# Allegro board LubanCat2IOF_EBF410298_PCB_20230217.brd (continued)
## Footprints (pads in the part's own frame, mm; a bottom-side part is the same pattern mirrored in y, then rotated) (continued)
USB-A-D
  round 1.651 hole 1: 1(3.5,-6.5) 2(1,-6.5) 3(-1,-6.5) 4(-3.5,-6.5) 7(3.5,-3.5) 8(1,-3.5) 9(-1,-3.5) 10(-3.5,-3.5)
  round 3.3 hole 2: 5(-6.55,-6.5) 6(6.55,-6.5) 11(-6.55,-0.7) 12(6.55,-0.7)
USON_10
  rect 0.3x0.55 smd: 1(-1,-0.4) 2(-0.5,-0.4) 4(0.5,-0.4) 5(1,-0.4) 6(1,0.4) 7(0.5,0.4) 9(-0.5,0.4) 10(-1,0.4)
  rect 0.4x0.55 smd: 3(0,-0.4) 8(0,0.4)
XH2P54-4P
  rect 1.45x1.45 hole 0.85: 1(-3.81,0)
  round 1.45 hole 0.85: 2(-1.27,0) 3(1.27,0) 4(3.81,0)
ZH1P5MM_TH_2P
  round 1.05 hole 0.65: 1(-0.75,0) 2(0.75,0)

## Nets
1V05_AVDD_PHY0: C84.1 C85.1 C86.1 C87.1 R114.2 U18.3(AVDD10_2) U18.8(AVDD10_1) U18.38(AVDD10)
1V05_AVDD_PHY1: C105.1 C106.1 C107.1 C108.1 R141.2 U19.3(AVDD10_2) U19.8(AVDD10_1) U19.38(AVDD10)
1V05_DVDD_PHY0: C82.1 C83.1 R113.1 U18.21(DVDD10)
1V05_DVDD_PHY1: C103.1 C104.1 R140.1 U19.21(DVDD10)
1V05_PHY0: C74.1 C75.1 L9.2 R113.2 R114.1
1V05_PHY1: C96.1 C97.1 L13.2 R140.2 R141.1
1V8_DVDD_PHY0: C72.1 C73.1 C81.1 L10.1 R88.1 R89.1 R90.1 R101.1 R102.1 R107.1 U18.28(DVDD_RG)
1V8_DVDD_PHY1: C94.1 C95.1 C102.1 L14.1 R115.1 R116.1 R117.1 R128.1 R129.1 R136.1 U19.28(DVDD_RG)
3V3_AVDD_PHY0: C91.1 C92.1 C93.1 L12.1 U18.11(AVDD33_1) U18.40(AVDD33)
3V3_AVDD_PHY1: C112.1 C113.1 C114.1 L16.1 U19.11(AVDD33_1) U19.40(AVDD33)
3V3_DVDD_PHY0: C88.1 C89.1 C90.1 L11.1 R28.2 R103.1 R109.2 R110.2 R184.1 U18.29(DVDD33)
3V3_DVDD_PHY1: C109.1 C110.1 C111.1 L15.1 R130.1 R133.2 R138.2 R139.2 R238.1 U19.29(DVDD33)
12V: C5.1 C6.1 C7.1 C8.1 C9.1 C10.1 C18.1 C19.1 C27.1 C160.1 C179.1 C180.1 C181.1 C182.1 C209.1 C210.1 C218.1 F1.2 J3.1 J29.26 J29.27 J29.28 J29.29 Q10.2(SOURCE) R205.1 R225.2 U1.3(VIN) U2.3(VIN) U5.3(VIN) U16.3(VIN) U41.3(VIN)
12V_IN: F1.1 J39.4
GND: C3.2 C4.2 C5.2 C6.2 C7.2 C8.2 C9.2 C10.2 C12.2 C13.2 C15.2 C16.2 C17.2 C18.2 C19.2 C21.2 C22.2 C23.2 C25.2 C26.2 C27.2 C28.2 C30.2 C31.2 C33.2 C34.2 C35.2 C36.2 C37.2 C38.2 C39.2 C40.2 C41.2 C42.2 C43.2 C44.2 C45.2 C46.2 C47.2 C48.2 C51.2 C52.2 C55.2 C56.2 C57.2 C58.2 C59.2 C63.2 C64.2 C65.2 C66.2 C67.2 C70.2 C71.2 C72.2 C73.2 C74.2 C75.2 C76.2 C77.2 C78.2 C79.2 C80.2 C81.2 C82.2 C83.2 C84.2 C85.2 C86.2 C87.2 C88.2 C89.2 C90.2 C91.2 C92.2 C93.2 C94.2 C95.2 C96.2 C97.2 C98.2 C99.2 C100.2 C101.2 C102.2 C103.2 C104.2 C105.2 C106.2 C107.2 C108.2 C109.2 C110.2 C111.2 C112.2 C113.2 C114.2 C115.2 C116.2 C117.2 C118.2 C119.2 C120.2 C121.2 C122.2 C129.2 C130.2 C131.2 C132.2 C133.2 C134.2 C135.2 C136.2 C137.2 C138.2 C141.2 C144.2 C145.2 C146.2 C147.2 C148.2 C149.2 C150.2 C151.2 C152.2 C153.2 C154.2 C155.2 C156.2 C157.2 C158.2 C159.2 C160.2 C161.2 C162.2 C163.2 C164.2 C165.2 C166.2 C167.2 C168.2 C169.2 C170.2 C171.2 C172.2 C173.2 C174.2 C175.2 C176.2 C179.2 C180.2 C181.2 C182.2 C183.2 C184.2 C185.2 C186.2 C187.2 C188.2 C189.2 C190.2 C191.2 C192.2 C193.2 C194.2 C195.2 C196.2 C197.2 C198.2 C199.2 C200.2 C201.2 C202.2 C203.2 C204.2 C207.2 C208.2 C209.2 C210.2 C212.2 C213.2 C216.2 C218.2 D1.1 D2.1 D3.1 D6.2 D7.2 D8.2 D9.2 D10.2 D11.2 D12.2 D13.2 D15.1 D16.1 D17.1 D18.1 D19.2 D20.1(A) D23.2 D24.1 D25.2 D26.2 D28.1 D29.2 D30.2 D31.2 D32.2 D33.2 D34.2 J1.2 J1.3 J2.3 J3.2 J3.4 J3.6 J4.6(VSS) J4.10(GND10) J4.11(GND11) J4.12(GND12) J4.13(GND13) J6.2 J8.2 J8.5 J9.4 J11.10(CHS) J12.4 J15.6 J16.2 J17.1(CONFIG_3) J17.3(GND1) J17.9(GND2) J17.15(GND3) J17.21(CONFIG_0) J17.27(GND4) J17.33(GND5) J17.39(GND_6) J17.45(GND_7) J17.51(GND_8) J17.57(GND_9) J17.71(GND_10) J17.73(GND_11) J17.75(CONFIG_2) J17.76(G1) J17.77(G2) J18.10(CHS) J19.4(GND1) J19.7(GND2) J19.13(GND1) J19.16(NC3) J20.4(GND) J20.10(GND) J21.2 J21.5 J21.8 J21.11 J21.17 J22.4 J22.18 J22.21 J22.23 J22.24 J22.25 J22.26 J23.6 J23.7 J23.8 J23.16 J23.19 J23.22 J23.25 J23.28 J23.31 J23.32 J24.4 J24.23 J24.24 J24.25 J24.26 J26.6 J26.7 J26.8 J26.16 J26.19 J26.22 J26.25 J26.28 J26.31 J26.32 J28.6 J29.2 J29.5 J29.8 J29.11 J29.15 J29.16 J29.18 J29.19 J29.20 J29.21 J29.31 J29.32 J33.1 J34.1(GND1) J34.4(GND2) J34.7(GND3) J34.S1(SH1) J34.S2(SH2) J35.4(GND9) J35.9(GND1) J35.15(GND2) J35.18(GND10) J35.21(GND3) J35.26(GND11) J35.27(GND4) J35.29(GND5) J35.34(GND12) J35.35(GND6) J35.37(GND7) J35.40(GND13) J35.43(GND8) J35.50(GND14) J35.53 J35.54 J36.A1(GND1) J36.A12(GND2) J36.B1(GND4) J36.B12(GND3) J38.7 J38.8 J38.9 J38.10 J38.11 J38.12 J38.18 J38.22 J38.24 J38.25 J38.26 J38.27 J38.32 J38.38 J38.39 J38.46 J38.53 J38.62 J38.67 J38.72 J38.81 J38.87 J38.90 J38.91 J38.96 J38.100 J38.106 J38.107 J38.116 J38.117 J38.122 J38.128 J38.135 J38.138 J38.141 J38.144 J38.154 J38.159 J38.164 J38.166 J38.167 J38.176 J38.194 J38.195 J38.204 J38.205 J38.211 J38.214 J38.221 J38.228 J38.229 J38.238 J38.239 J38.248 J38.249 J38.258 J38.263 J38.272 J38.285 J38.288 J38.294 J38.299 J38.300 J38.306 J38.311 J38.312 J38.315 J38.316 J39.2 J39.3 L2.2 L19.2 L20.2 L21.2 LED1.2(CATHODE) Q4.2(EMITTER) Q14.2(SOURCE) R3.2 R7.2 R8.2 R12.2 R13.2 R15.2 R17.2 R27.2 R40.2 R41.2 R69.2 R70.2 R74.2 R75.2 R79.2 R82.2 R97.2 R98.2 R99.2 R100.2 R106.2 R108.2 R112.2 R121.2 R125.2 R126.2 R127.2 R131.2 R135.2 R137.2 R142.2 R143.2 R144.2 R155.2 R157.2 R159.2 R162.2 R163.2 R171.2 R173.2 R175.2 R176.2 R177.2 R183.2 R186.2 R188.1 R190.2 R192.2 R196.2 R197.2 R198.2 R199.2 R202.2 R203.2 R207.2 R212.2 R215.2 R216.2 R220.2 R234.2 R237.2 SS5.1(NC_1) SS6.1(NC_1) SS7.1(NC_1) SS8.1(NC_1) SS9.1(NC_1) SS10.1(NC_1) SS11.1(NC_1) SW1.1(A1) SW1.3(GND1) SW2.1(A1) SW2.3(GND1) SW3.1(A1) SW3.3(GND1) U1.1(GND) U2.1(GND) U3.1(GND1) U3.4(GND2) U4.1(\\O\E) U4.3(GND) U5.1(GND) U6.4(GND) U7.1(GND) U8.5(GND) U9.2(GND) U9.8(S) U10.2(GND) U10.8(S) U11.15(GND) U12.1(\\O\E) U12.3(GND) U13.5(GND) U14.5(GND) U14.8(SH1) U14.9(SH2) U14.10(SH3) U14.11(SH4) U15.2 U16.1(GND) U17.4(GND) U18.41(GND) U19.41(GND) U20.1(GND) U21.9(GNDXD) U21.16(GNDODA) U22.3(GND1) U22.8(GND2) U23.3(GND1) U23.8(GND2) U24.2(GND) U25.2(GND) U26.2(GND) U28.25(VSS) U29.2(GND) U30.3(GND1) U30.8(GND2) U31.3(GND1) U31.8(GND2) U32.3(GND1) U32.8(GND2) U33.2(GND) U34.2(GND) U35.2(GND) U36.2(GND) U37.2(GND) U38.2(GND) U39.2(GND) U40.2(GND) U41.1(GND) Y1.2(GND1) Y1.4(GND2) Y2.2(GND1) Y2.4(GND2) Y3.2(GND1) Y3.4(GND2) Y4.2(GND1) Y4.4(GND2) Z1.2 Z2.2
VCC3V3_SD: C28.1 C30.1 J4.4(VDD) J38.17 J38.19
VCC5V0_SYS: C24.2 C25.1 C26.1 J38.1 J38.2 J38.3 J38.4 J38.5 J38.6 L3.2 R4.1 R11.2
VCC5V0_USB: C140.2 C141.1 C159.1 L17.2 R235.2 U24.5(IN) U25.5(IN) U26.5(IN) U29.5(IN)
VCC5V0_USB20_HOST2: C144.1 C145.1 J19.10(VBUS) U24.1(OUT)
VCC5V0_USB20_HUB: C154.1 C155.1 C161.1 C162.1 C164.1 C165.1 J20.1(VBUS) J20.7(VBUS) U28.19(VDD5) U29.1(OUT)
VCC5V0_USB30_HOST: C148.1 C149.1 J19.1(VBUS) U26.1(OUT)
VCC_1V8: C22.1 C23.1 J38.13 J38.15 L10.2 L14.2 Q1.1(GATE) Q2.1(GATE) R24.1 R25.1 R45.1 R46.1 U6.8(VCC)
VCCA_1V8: J38.14 J38.16 R219.1
VCCIO_ACODEC: J38.21 J38.23 R210.1 R213.1
VDD_3V3: C12.1 C13.1 C14.2 C17.1 C21.1 C37.1 C40.1 D21.2 J3.5 L5.1 L6.1 L7.2 L11.2 L12.2 L15.2 L16.2 L35.2 Q6.1(GATE) Q8.1(GATE) R2.2 R6.2 R31.1 R32.1 R33.1 R35.1 R47.1 R48.1 R66.2 R72.1 R146.1 R147.1 R178.1 R180.1 R181.1 R236.2 U4.5(VCC) U9.5(VIO) U10.5(VIO) U12.5(VCC) U35.5(IN) U37.5(IN) U38.5(IN) U40.5(IN)
VDD_3V3_EDP_LCD: C183.1 C184.1 J29.12 J29.13 R187.1 U37.1(OUT)
VDD_3V3_EDP_TP: C202.1 C203.1 J28.1 R193.1 R194.1 U38.1(OUT)
VDD_5V: C2.2 C3.1 C4.1 C36.1 C38.1 C41.1 C43.1 C46.1 C79.1 C80.1 D14.1 J3.3 L1.2 Q3.2(SOURCE) Q7.1(GATE) R1.2 R9.1 U7.3(VIN) U9.3(VCC) U10.3(VCC) U20.3(VIN) U33.5(IN) U34.5(IN) U36.5(IN) U39.5(IN)
VDD_CAM0_5V: C169.1 C170.1 C171.1 J22.1 J22.2 J22.3 U33.1(OUT)
VDD_CAM1_5V: C173.1 C174.1 C175.1 J24.1 J24.2 J24.3 U36.1(OUT)
VDD_LCD0_3V3: C185.1 C190.1 C191.1 J23.4 J23.5 R167.1 R222.1 U35.1(OUT)
VDD_LCD0_5V: C186.1 C187.1 C188.1 J23.1 J23.2 J23.3 U34.1(OUT)
VDD_LCD1_3V3: C196.1 C198.1 C199.1 J26.4 J26.5 R223.1 R224.1 U40.1(OUT)
VDD_LCD1_5V: C194.1 C195.1 C197.1 J26.1 J26.2 J26.3 U39.1(OUT)
BAT_RTC: C67.1 D21.1 D24.2 J16.1
CAM0_NRST: J22.22 J38.158
CAM0_PWDN: J22.15 J38.156
CAM0_PWR_EN: J38.309 R174.1
CAM1_NRST: J24.22 J38.162
CAM1_PWDN: J24.15 J38.160
CAM1_PWR_EN: J38.307 R185.1
CAN1_H: J5.1 R39.1 U9.7(CANH)
CAN1_L: J5.2 R39.2 U9.6(CANL)
CAN1_RX_M1: J38.275 U9.4(RXD)
CAN1_TX_M1: J38.273 U9.1(TXD)
CAN2_H: J5.3 R42.1 U10.7(CANH)
CAN2_L: J5.4 R42.2 U10.6(CANL)
CAN2_RX: Q2.3(DRAIN) R48.2 U10.4(RXD)
CAN2_RX_M0: J38.172 Q2.2(SOURCE) R46.2
CAN2_TX: Q1.3(DRAIN) R47.2 U10.1(TXD)
CAN2_TX_M0: J38.174 Q1.2(SOURCE) R45.2
CC1: D27.2 J36.A5(CC1)
CC2: D27.1 J36.B5(CC2)
CTP0_INT: J23.11 J38.173 R167.2
CTP0_RST: J23.12 J38.171 R222.2
CTP1_INT: J26.11 J38.255 R223.2
CTP1_RST: J26.12 J38.257 R224.2
DGB_RX: J2.2 R36.1 Z1.1
DGB_TX: J2.1 R23.1 Z2.1
DSI0_RST: J23.15 J38.175
DSI0_TE: J38.169 R204.1
DSI1_RST: J26.15 J38.259
DSI1_TE: J38.261 R208.1
EDP_AUXN: C178.2 J29.10 R188.2
EDP_AUXP: C177.2 J29.9 R187.2
EDP_BL_EN: J29.22 J38.233
EDP_BL_PWM: J29.23 J38.177
EDP_HPDIN_M0: J29.17 J38.98
EDP_LCD_PWR_EN: J38.305 R189.2
EDP_TP_INT: J28.2 J38.253 R193.2
EDP_TP_PWR_EN: J38.303 R191.1
EDP_TP_RESET: J28.3 J38.251 R194.2
EDP_TX_AUXN: C178.1 J38.94
EDP_TX_AUXP: C177.1 J38.92
EDP_TX_D0N: J29.6 J38.76
EDP_TX_D0P: J29.7 J38.74
EDP_TX_D1N: J29.3 J38.80
EDP_TX_D1P: J29.4 J38.78
EXT_PWR_EN: J38.31 R8.1 U2.5(EN)
FAN_CTRL: J38.183 R10.1
FSPI_CLK: J38.41 U6.6(CLK)
FSPI_CS0N: J38.49 U6.1(C\S\)
FSPI_D0: J32.1 J38.51 U6.5(DI/IO0)
FSPI_D1: J38.47 U6.2(DO/IO1)
FSPI_D2: J38.43 R24.2 U6.3(W\P\/IO2)
FSPI_D3: J38.45 R25.2 U6.7(HOLD/IO3)
GMAC0_INT: J38.35 R104.1
GMAC0_MCLKINOUT: J38.89 R105.1 R106.1
GMAC0_MDC: J38.83 R101.2 U18.13(MDC)
GMAC0_MDIO: J38.85 R102.2 U18.14(MDIO)
GMAC0_RSTN: D22.2 J38.37
GMAC0_RXCLK: J38.69 R95.1 R98.1
GMAC0_RXD0: J38.75 R88.2 R91.1
GMAC0_RXD1: J38.79 R89.2 R92.1
GMAC0_RXD2: J38.71 R93.1 R97.1
GMAC0_RXD3: J38.73 R90.2 R94.1
GMAC0_RXDV_CRS: J38.77 R96.1 R99.1
GMAC0_TXCLK: J38.65 U18.20(TXC)
GMAC0_TXD0: J38.59 U18.18(TXD0)
GMAC0_TXD1: J38.57 U18.17(TXD1)
GMAC0_TXD2: J38.61 U18.16(TXD2)
GMAC0_TXD3: J38.63 U18.15(TXD3)
GMAC0_TXEN: J38.55 U18.19(TXCTL)
GMAC1_INT: J38.179 R132.1
GMAC1_MCLKINOUT_M1: J38.286 R134.1 R135.1
GMAC1_MDC_M1: J38.292 R128.2 U19.13(MDC)
GMAC1_MDIO_M1: J38.290 R129.2 U19.14(MDIO)
GMAC1_RSTN: D35.2 J38.181
GMAC1_RXCLK_M1: J38.289 R117.2 R123.1
GMAC1_RXD0_M1: J38.293 R115.2 R118.1
GMAC1_RXD1_M1: J38.297 R116.2 R119.1
GMAC1_RXD2_M1: J38.287 R120.1 R125.1
GMAC1_RXD3_M1: J38.291 R122.1 R126.1
GMAC1_RXDV_CRS_M1: J38.295 R124.1 R127.1
GMAC1_TXCLK_M1: J38.274 U19.20(TXC)
GMAC1_TXD0_M1: J38.276 U19.18(TXD0)
GMAC1_TXD1_M1: J38.278 U19.17(TXD1)
GMAC1_TXD2_M1: J38.284 U19.16(TXD2)
GMAC1_TXD3_M1: J38.282 U19.15(TXD3)
GMAC1_TXEN_M1: J38.280 U19.19(TXCTL)
HDMI_5V: C168.1 D14.2 D28.2 J21.18 R179.1 R182.1
HDMI_GND_CHASSIS: J21.G1(20) J21.G2(21) J21.G3(22) J21.G4(23) R177.1
HDMI_TX0N_PORT: J21.9 J38.198 U32.2(D1-) U32.9(NC2)
HDMI_TX0P_PORT: J21.7 J38.196 U32.1(D1+) U32.10(NC1)
HDMI_TX1N_PORT: J21.6 J38.192 U31.5(D2-) U31.6(NC4)
HDMI_TX1P_PORT: J21.4 J38.190 U31.4(D2+) U31.7(NC3)
HDMI_TX2N_PORT: J21.3 J38.188 U31.2(D1-) U31.9(NC2)
HDMI_TX2P_PORT: J21.1 J38.186 U31.1(D1+) U31.10(NC1)
HDMI_TX_CEC_PORT: D18.2 J21.13 Q7.3(DRAIN)
HDMI_TX_HPD_PORT: D15.2 J21.19 R172.2 R176.1
HDMI_TX_HPDIN: J38.184 R172.1
HDMI_TXCLKN_PORT: J21.12 J38.202 U32.5(D2-) U32.6(NC4)
HDMI_TXCLKP_PORT: J21.10 J38.200 U32.4(D2+) U32.7(NC3)
HDMI_TXDDC_SCL_PORT: D17.2 J21.15 Q6.3(DRAIN) R179.2
HDMI_TXDDC_SDA_PORT: D16.2 J21.16 Q8.3(DRAIN) R182.2
HDMITX_CEC_M0: J38.182 Q7.2(SOURCE) R180.2
HDMITX_SCL: J38.178 Q6.2(SOURCE) R178.2
HDMITX_SDA: J38.180 Q8.2(SOURCE) R181.2
HP_DET: C213.1 J38.121 R211.1
HP_SNS: J25.5 J27.5 J38.42 R212.1 R216.1
HPL_OUT: C214.1 J38.40
HPR_OUT: C215.1 J38.44
HUB_3V3: C156.1 C157.1 R164.2 R165.2 R166.2 R168.2 R169.1 U28.20(VDD33F)
I2C0_SCL: J38.111 U17.6(SCL)
I2C0_SDA: J38.109 U17.5(SDA)
I2C1_SCL: J22.6 J23.9 J38.115 R35.2
I2C1_SDA: J22.5 J23.10 J38.113 R33.2
I2C5_SCL_M0: J24.6 J26.9 J28.4 J38.313 R147.2
I2C5_SDA_M0: J24.5 J26.10 J28.5 J38.314 R146.2
LCD0_BL_PWM: J23.13 J38.187
LCD0_PWR_EN: J38.235 R195.1
LCD1_BL_PWM: J26.13 J38.185
LCD1_PWR_EN: J38.237 R200.2
LED_USR: J38.168 LED2.2(CATHODE)
M2PCIE_3V3: C69.2 C70.1 C71.1 C115.1 C116.1 C117.1 C118.1 C119.1 C120.1 C121.1 C122.1 C129.1 C130.1 C131.1 C136.1 J17.2(3.3V_1) J17.4(3.3V_2) J17.12(3.3V_3) J17.14(3.3V_4) J17.16(3.3V_5) J17.18(3.3V_6) J17.70(3.3V_7) J17.72(3.3V_8) J17.74(3.3V_9) L8.2 R73.2 R80.2 R81.2 R83.1 R84.1 R85.1 R86.1 R145.2 U21.1(VDDXD)
M2PCIE_PWR_EN: J38.133 R76.2
MDIN0_PHY0: J11.3(TD1-) U18.2(MDIN0)
MDIN0_PHY1: J18.3(TD1-) U19.2(MDIN0)
MDIN1_PHY0: J11.7(RD1-) U18.5(MDIN1)
MDIN1_PHY1: J18.7(RD1-) U19.5(MDIN1)
MDIN2_PHY0: J11.6(TD2-) U18.7(MDIN2)
MDIN2_PHY1: J18.6(TD2-) U19.7(MDIN2)
MDIN3_PHY0: J11.9(RD2-) U18.10(MDIN3)
MDIN3_PHY1: J18.9(RD2-) U19.10(MDIN3)
MDIP0_PHY0: J11.2(TD1+) U18.1(MDIP0)
MDIP0_PHY1: J18.2(TD1+) U19.1(MDIP0)
MDIP1_PHY0: J11.4(RD1+) U18.4(MDIP1)
MDIP1_PHY1: J18.4(RD1+) U19.4(MDIP1)
MDIP2_PHY0: J11.5(TD2+) U18.6(MDIP2)
MDIP2_PHY1: J18.5(TD2+) U19.6(MDIP2)
MDIP3_PHY0: J11.8(RD2+) U18.9(MDIP3)
MDIP3_PHY1: J18.8(RD2+) U19.9(MDIP3)
MIC1_INN: C217.2 D30.1 J27.3 J27.4 J30.1 J38.34 R215.1
MIC1_INP: C217.1 D29.1 J27.1 J27.2 J30.2 J38.36 R214.2
MINIPCIE_3V3: C32.1 C33.1 C34.1 C35.1 C55.1 C56.1 C57.1 C58.1 J35.2(VBAT1) J35.24(VBAT5) J35.39(VBAT2) J35.41(VBAT3) J35.52(VBAT4) L4.2 R14.1 R22.1
MINIPCIE_NWDISABLE: J38.243 R62.2
MINIPCIE_PWR_EN: J38.245 R16.1
MIPI_CSI_RX_CLK0N: J22.10 J38.240
MIPI_CSI_RX_CLK0P: J22.9 J38.242
MIPI_CSI_RX_CLK1N: J24.10 J38.244
MIPI_CSI_RX_CLK1P: J24.9 J38.246
MIPI_CSI_RX_D0N: J22.12 J38.230
MIPI_CSI_RX_D0P: J22.11 J38.232
MIPI_CSI_RX_D1N: J22.8 J38.234
MIPI_CSI_RX_D1P: J22.7 J38.236
MIPI_CSI_RX_D2N: J38.250 R227.1 R233.1
MIPI_CSI_RX_D2P: J38.252 R226.1 R232.1
MIPI_CSI_RX_D3N: J38.254 R229.1 R231.1
MIPI_CSI_RX_D3P: J38.256 R228.1 R230.1
MIPI_DSI_TX0_CLKN: J23.24 J38.216
MIPI_DSI_TX0_CLKP: J23.23 J38.218
MIPI_DSI_TX0_D0N: J23.27 J38.206
MIPI_DSI_TX0_D0P: J23.26 J38.208
MIPI_DSI_TX0_D1N: J23.21 J38.210
MIPI_DSI_TX0_D1P: J23.20 J38.212
MIPI_DSI_TX0_D2N: J23.18 J38.220
MIPI_DSI_TX0_D2P: J23.17 J38.222
MIPI_DSI_TX0_D3N: J23.30 J38.224
MIPI_DSI_TX0_D3P: J23.29 J38.226
MIPI_DSI_TX1_CLKN: J26.24 J38.207
MIPI_DSI_TX1_CLKP: J26.23 J38.209
MIPI_DSI_TX1_D0N: J26.27 J38.197
MIPI_DSI_TX1_D0P: J26.26 J38.199
MIPI_DSI_TX1_D1N: J26.21 J38.201
MIPI_DSI_TX1_D1P: J26.20 J38.203
MIPI_DSI_TX1_D2N: J26.18 J38.213
MIPI_DSI_TX1_D2P: J26.17 J38.215
MIPI_DSI_TX1_D3N: J26.30 J38.217
MIPI_DSI_TX1_D3P: J26.29 J38.219
OE: R83.2 U21.8(OE)
ON/OFF_KEY: C64.1 D2.2 J38.33 SW2.2(B1)
PCIE20_CLKREQN_M1: J38.231 R30.1
PCIE20_PERSTN_M1: J38.247 R63.2
PCIE20_REFCLKN: J35.11(VDD-EXT) J38.140
PCIE20_REFCLKP: J35.13(RESERVED) J38.142
PCIE20_RXN: J35.23(UART-RXD) J38.150
PCIE20_RXP: J35.25(UART-RTS) J38.152
PCIE20_TXN: C53.1 J38.146
PCIE20_TXP: C54.1 J38.148
PCIE20_WAKEN_M1: J38.227 R29.1
PCIE30_REFCLKN_IN: J38.139 R78.2 R79.1
PCIE30_REFCLKP_IN: J38.137 R77.2 R82.1
PCIE30_RX0N: J17.41(SATA-/B+/PERN0) J38.153
PCIE30_RX0P: J17.43(SATA-/B-/PERP0) J38.151
PCIE30_RX1N: J17.29(PERN1) J38.157
PCIE30_RX1P: J17.31(PERP1) J38.155
PCIE30_TX0N: C125.1 J38.145
PCIE30_TX0P: C126.1 J38.143
PCIE30_TX1N: C123.1 J38.149
PCIE30_TX1P: C124.1 J38.147
PCIE30X2_CLKREQN_M1: J17.52(CLKREQ#) J38.161
PCIE30X2_PERSTN_M1: J17.50(PERST#) J38.165
PCIE30X2_WAKEN_M1: J17.54(PEWAKE#) J38.163
PDN: R84.2 U21.7(PDN)
PE_TXN: C53.2 J35.31(UART-TXD)
PE_TXP: C54.2 J35.33(PERST2)
PETN0: C125.2 J17.47(SATA-/A-/PETN0)
PETN1: C123.2 J17.35(PETN1)
PETP0: C126.2 J17.49(SATA-/A+/PETP0)
PETP1: C124.2 J17.37(PETP1)
PHY0_CLKOUT125: R105.2 U18.35(CLKOUT)
PHY0_LED1: J11.14(YELA) R108.1 U18.33(LED1)
PHY0_LED2: J11.12(GRLC) R109.1 U18.34(LED2)
PHY1_CLKOUT125: R134.2 U19.35(CLKOUT)
PHY1_LED1: J18.14(YELA) R137.1 U19.33(LED1)
PHY1_LED2: J18.12(GRLC) R138.1 U19.34(LED2)
PWM3_IR: J38.189 R34.1
RECOVERY_KEY: J38.60 R26.2
REF_CLKN: C127.1 R111.2 R112.1
REF_CLKP: C128.1 R87.2 R142.1
REFCLKN: C127.2 J17.53(REFCLKN)
REFCLKP: C128.2 J17.55(REFCLKP)
RESET_KEY: C63.1 D1.2 J38.29 SW1.2(B1)
RS232_3V3: C42.1 L7.1 U11.16(VCC)
RS232_R1IN: J8.4 U11.13(R1IN)
RS232_R1OUT: J13.1 U11.12(R1OUT)
RS232_R2IN: J8.1 U11.8(R2IN)
RS232_R2OUT: J14.1 U11.9(R2OUT)
RS232_T1IN: J13.2 U11.11(T1IN)
RS232_T1OUT: J8.6 U11.14(T1OUT)
RS232_T2IN: J14.2 U11.10(T2IN)
RS232_T2OUT: J8.3 U11.7(T2OUT)
RS485_1_3V3: C39.1 D4.1 L5.2 U8.8(VCC)
RS485_1_A: J10.2 R37.1 R38.2 U8.6(A)
RS485_1_B: J10.1 R38.1 R41.1 U8.7(B)
RS485_1_DIR: J38.223 R40.1 U8.2(R\E\) U8.3(DE)
RS485_2_3V3: C44.1 D5.1 L6.2 U13.8(VCC)
RS485_2_A: J10.4 R67.1 R68.2 U13.6(A)
RS485_2_B: J10.3 R68.1 R70.1 U13.7(B)
RS485_2_DIR: J38.225 R69.1 U13.2(R\E\) U13.3(DE)
RX8010_NIRQ1: J38.123 R72.2 U17.7(/IRQ1)
S0: R86.2 U21.2(S0)
S1: R85.2 U21.3(S1)
S2: R143.1 U21.4(S2)
SARADC_VIN1: J38.56 R55.1
SARADC_VIN3: J38.58 R219.2 R220.1
SARADC_VIN4: J38.52 R56.1
SARADC_VIN5: J38.54 R58.1
SARADC_VIN6: J38.48 R59.1
SARADC_VIN7: J38.50 R71.1
SATA0_RXN: C62.1 J38.108
SATA0_RXP: C211.1 J38.110
SATA0_TXN: C61.1 J38.112
SATA0_TXP: C60.1 J38.114
SATA0RXN: C62.2 J34.5(RXDN)
SATA0RXP: C211.2 J34.6(RXDP)
SATA0TXN: C61.2 J34.3(TXDN)
SATA0TXP: C60.2 J34.2(TXDP)
SATA_5V: C206.2 C207.1 C208.1 J1.1 L22.2 R201.2
SATA_12V: C59.1 C212.1 J1.4 Q10.3(DRAIN)
SATA_PWR_EN: J38.119 R206.1 R209.2
SDMMC0_CLK: J38.95 R54.1
SDMMC0_CMD: J38.97 R53.1
SDMMC0_D0: J38.99 R57.1
SDMMC0_D1: J38.105 R60.1
SDMMC0_D2: J38.93 R51.1
SDMMC0_D3: J38.103 R52.1
SDMMC0_DET: J38.101 R61.1
SIM_CLK0: J35.12(USIM-CLK) R20.1
SIM_DATA0: J35.10(USIM-DATA) R21.1
SIM_RST0: J35.14(USIM-RST) R19.1
SIM_VDD: J35.8(USIM-VDD) R18.1 U14.1(VCC) U15.6
SPKN_OUT: J38.30 R218.1
SPKP_OUT: J38.28 R217.1
U7_RX: J9.3 J13.5
U7_TX: J9.2 J13.6
U9_RX: J12.3 J14.5
U9_TX: J12.2 J14.6
UART2_RX: R36.2 U12.2(A)
UART2_RX_M0_DEBUG: J38.193 U12.4(Y)
UART2_TX: R23.2 U4.4(Y)
UART2_TX_M0_DEBUG: J38.191 U4.2(A)
UART3_RX_M1: J38.271 U8.1(RXD)
UART3_TX_M1: J38.269 U8.4(TXD)
UART4_RX_M1: J38.267 U13.1(RXD)
UART4_TX_M1: J38.265 U13.4(TXD)
UART7_RX: D9.1 J13.3 R50.2
UART7_RX_M1: J38.283 R50.1
UART7_TX: D8.1 J13.4 R49.2
UART7_TX_M1: J38.281 R49.1
UART9_RX: D7.1 J14.3 R44.2
UART9_RX_M1: J38.279 R44.1
UART9_TX: D6.1 J14.4 R43.2
UART9_TX_M1: J38.277 R43.1
USB2_HOST2_DM: J38.304 R152.2
USB2_HOST2_DP: J38.302 R153.2
USB2_HOST3_DM: J38.298 U28.14(DMU)
USB2_HOST3_DP: J38.296 U28.15(DPU)
USB3_HOST1_DM: J38.126 R148.2
USB3_HOST1_DP: J38.124 R149.2
USB3_HOST1_SSRXN: J38.130 R150.2
USB3_HOST1_SSRXP: J38.132 R151.2
USB3_HOST1_SSTXN: C142.2 J38.134
USB3_HOST1_SSTXP: C143.2 J38.136
USB3_OTG0_DM: D26.1 J36.A7(DN1) J36.B7(DN2) J38.104
USB3_OTG0_DP: D25.1 J36.A6(DP1) J36.B6(DP2) J38.102
USB3_OTG0_ID: J38.118 R160.2
USB3_OTG0_VBUSDET: J38.120 R158.2 R159.1
USB20_DM1: J19.11(D-) R152.1 U22.1(D1+) U22.10(NC1)
USB20_DP1: J19.12(D+) R153.1 U22.2(D1-) U22.9(NC2)
USB20_HOST2_PWR_EN: J38.131 R154.1
USB20_HUB_PWR_EN: J38.301 R170.1
USB30_DM: J19.2(D-) R148.1 U23.4(D2+) U23.7(NC3)
USB30_DP: J19.3(D+) R149.1 U23.5(D2-) U23.6(NC4)
USB30_HOST1_PWR_EN: J38.129 R156.1
USB30_RXN: J19.5(RX-) R150.1 U23.1(D1+) U23.10(NC1)
USB30_RXP: J19.6(RX+) R151.1 U23.2(D1-) U23.9(NC2)
USB30_TXN: C142.1 J19.8(TX-) U22.4(D2+) U22.7(NC3)
USB30_TXP: C143.1 J19.9(TX+) U22.5(D2-) U22.6(NC4)
USB_HUB_DM1: J20.2(D-) U28.11(DM1) U30.2(D1-) U30.9(NC2)
USB_HUB_DM2: J20.8(D-) U28.9(DM2) U30.5(D2-) U30.6(NC4)
USB_HUB_DM3: R64.2 U28.7(DM3)
USB_HUB_DP1: J20.3(D+) U28.12(DP1) U30.1(D1+) U30.10(NC1)
USB_HUB_DP2: J20.9(D+) U28.10(DP2) U30.4(D2+) U30.7(NC3)
USB_HUB_DP3: R65.2 U28.8(DP3)
USB_OTG_VBUS: C151.1 C152.1 D23.1 J36.A4(VBUS1) J36.A9(VBUS2) J36.B4(VBUS4) J36.B9(VBUS3) R158.1 U25.1(OUT)
USB_OTG_VBUS_EN: J38.127 R161.1
N28501: C20.1 U5.6(BOOT)
N28533: C20.2 L3.1 U5.2(SW)
N28611: C24.1 R11.1 R13.1 U5.4(FB)
N15580021: R91.2 U18.25(RXD0)
N15580025: R92.2 U18.24(RXD1)
N15580029: R93.2 U18.23(RXD2)
N15580033: R94.2 U18.22(RXD3)
N15580037: R95.2 U18.27(RXC)
N15580041: R96.2 U18.26(RXCTL)
N15582684: R103.2 R104.2 U18.31(INTB)
N15584123: C77.1 U18.36(XTAL_IN) Y3.3
N15584130: C76.1 U18.37(XTAL_OUT) Y3.1
N15584385: C78.1 D22.1 R107.2 R184.2 U18.12(PHYRSTB)
N15584944: R110.1 U18.32(LED0)
N15590150: L9.1 U18.30(REG_OUT)
N15590489: R100.1 U18.39(RSET)
N15599533: R118.2 U19.25(RXD0)
N15599537: R119.2 U19.24(RXD1)
N15599541: R120.2 U19.23(RXD2)
N15599545: R122.2 U19.22(RXD3)
N15599549: R123.2 U19.27(RXC)
N15599553: R124.2 U19.26(RXCTL)
N15600826: R130.2 R132.2 U19.31(INTB)
N15601838: C98.1 U19.37(XTAL_OUT) Y4.1
N15601846: C99.1 U19.36(XTAL_IN) Y4.3
N15602147: C101.1 D35.1 R136.2 R238.2 U19.12(PHYRSTB)
N15602572: R139.1 U19.32(LED0)
N15603170: C100.1 J18.1(CT)
N15605093: L13.1 U19.30(REG_OUT)
N15605512: R121.1 U19.39(RSET)
N15772454: J26.14 R208.2
N15774097: J23.14 R204.2
N16795890: R12.1 R225.1 U5.5(EN)
N17344359: J39.1 J39.5 L2.1
N17345181: C11.2 L35.1 U2.2(SW)
N17345183: C14.1 R6.1 R7.1 U2.4(FB)
N17345235: C11.1 U2.6(BOOT)
N17366990: C1.1 U1.6(BOOT)
N17366996: C1.2 L1.1 U1.2(SW)
N17367006: C2.1 R1.1 R3.1 U1.4(FB)
N17371141: LED1.1(ANODE) R4.2
N17385739: LED2.1(ANODE) R31.2
N17407470: J4.1(DAT2) R51.2
N17407472: J4.7(DAT0) R57.2
N17407474: J4.5(CLK) R54.2
N17407476: J4.3(CMD) R53.2
N17407478: J4.2(CD/DAT3) R52.2
N17407480: J4.8(DAT1) R60.2
N17407510: J4.9(CD) R61.2
N17408573: C31.1 J11.1(CT)
N17409816: C29.1 L4.1 U7.2(SW)
N17409833: R16.2 R17.1 U7.5(EN)
N17409879: C32.2 R14.2 R15.1 U7.4(FB)
N17410026: C29.2 U7.6(BOOT)
N17410340: C52.1 R19.2 U14.2(RST) U15.5
N17410342: C51.1 R20.2 U14.3(CLK) U15.4
N17410344: C47.1 R18.2 R21.2 U14.7(I/O) U15.1
N17411312: J35.1(MIC-P) R22.2 R29.2
N17411326: J35.7(SPK-N) R30.2
N17411361: J35.20(W-DISABLE) R62.1
N17411393: J35.22(PERST1) R63.1
N17411481: J35.38(USB-D+) R65.1
N17411507: J35.36(USB-D-) R64.1
N17438974: D4.2 R37.2
N17440531: D5.2 R67.2
N17441588: C49.1 U11.3(C1-)
N17441590: C49.2 U11.1(C1+)
N17441592: C50.1 U11.5(C2-)
N17441594: C50.2 U11.4(C2+)
N17441596: C48.1 U11.6(V-)
N17441598: C45.1 U11.2(V+)
N17468430: C66.1 D21.3 U17.8(VDD)
N17485809: R75.1 R76.1 U20.5(EN)
N17485853: C68.1 U20.6(BOOT)
N17485857: C68.2 L8.1 U20.2(SW)
N17485876: C69.1 R73.1 R74.1 U20.4(FB)
N17487342: J17.38(DEVSLP) R81.1
N17487441: J17.10(DAS/DSS) R80.1
N17494240: J19.19(SH1) J19.20(SH2) J19.21(SH1) J19.22(SH2) L19.1
N17495021: C147.1 R156.2 U26.4(EN)
N17495041: R157.1 U26.3(ISET)
N17495139: C146.1 R154.2 U24.4(EN)
N17495165: R155.1 U24.3(ISET)
N17495663: J36.C1(SH1) J36.C2(SH2) J36.C3(SH3) J36.C4(SH4) L20.1
N17495859: D27.3 R160.1
N17496265: R162.1 U25.3(ISET)
N17496334: C150.1 R161.2 U25.4(EN)
N17505436: R163.1 U28.13(REXT)
N17505526: R164.1 U28.16(XRSTJ)
N17505593: R165.1 U28.18(BUSJ)
N17505596: C153.1 R166.1 U28.17(VBUSM)
N17506485: R168.1 U28.21(DRV)
N17506866: C158.1 R169.2 U28.1(OVCJ)
N17515649: C138.1 U28.3(XOUT) Y2.1
N17515683: C137.1 U28.4(XIN) Y2.3
N17516865: J20.5(SH1) J20.6(SH2) J20.11(SH1) J20.12(SH2) L21.1
N17517489: C163.1 R170.2 U29.4(EN)
N17517506: R171.1 U29.3(ISET)
N17532429: D19.1 J15.1 R55.2
N17532431: D13.1 J15.2 R56.2
N17532433: D12.1 J15.3 R58.2
N17532435: D11.1 J15.4 R59.2
N17532437: D10.1 J15.5 R71.2
N17536330: C15.1 C16.1 R66.1 U3.2(VCC)
N17536407: R32.2 R34.2 U3.3(OUT)
N17536851: C65.1 D3.2 R26.1 SW3.2(B1)
N17545096: C172.1 R174.2 U33.4(EN)
N17545112: R175.1 U33.3(ISET)
N17546367: J24.8 R231.2
N17546373: J24.12 R233.2
N17546399: J24.7 R230.2
N17546411: J24.11 R232.2
N17548144: C176.1 R185.2 U36.4(EN)
N17548162: R186.1 U36.3(ISET)
N17550903: R190.1 U37.3(ISET)
N17550993: C201.1 R189.1 U37.4(EN)
N17558620: R192.1 U38.3(ISET)
N17558699: C204.1 R191.2 U38.4(EN)
N17562506: C189.1 C192.1 R195.2 U34.4(EN) U35.4(EN)
N17562520: R196.1 U34.3(ISET)
N17562633: R197.1 U35.3(ISET)
N17563970: C193.1 C200.1 R200.1 U39.4(EN) U40.4(EN)
N17564290: R198.1 U39.3(ISET)
N17565184: R199.1 U40.3(ISET)
N17577061: R202.1 R209.1 U41.5(EN)
N17577092: C205.1 U41.6(BOOT)
N17577104: C205.2 L22.1 U41.2(SW)
N17577114: C206.1 R201.1 R203.1 U41.4(FB)
N17577685: Q10.1(GATE) Q14.3(DRAIN) R205.2
N17577722: Q14.1(GATE) R206.2 R207.1
N17590789: C215.2 D34.1 J25.3 J25.4
N17590802: C214.2 D33.1 J25.2 R211.2
N17590849: J25.1 R210.2
N17609931: C216.1 R213.2 R214.1
N17615054: D31.1 J31.1 R217.2
N17615057: D32.1 J31.2 R218.2
N17639389: C132.1 U21.5(X1) Y1.1
N17639396: R144.1 U21.10(IREF)
N17639427: C134.1 C135.1 R145.1 U21.15(VDDODA)
N17639486: R77.1 U21.20(CLK0P)
N17639523: R78.1 U21.19(CLK0N)
N17639615: R87.1 U21.18(CLK1P)
N17639617: R111.1 U21.17(CLK1N)
N17639713: C133.1 R221.1 Y1.3
N17683065: R2.1 U1.5(EN)
N17697748: R221.2 U21.6(X2)
N17699685: J11.11(GRLA) R28.1
N17699996: J11.13(YELC) R27.1
N17700387: J18.11(GRLA) R133.1
N17700720: J18.13(YELC) R131.1
N17737040: J22.16 R226.2
N17737043: J22.17 R227.2
N17737126: J22.19 R228.2
N17737138: J22.20 R229.2
N17802924: Q3.1(GATE) Q4.3(COLLECTOR) R9.2
N17802940: Q4.1(BASE) R10.2 R234.1
N17802978: D20.2(K) J6.1 R5.2
N17803061: Q3.3(DRAIN) R5.1
N17804550: R236.1 U16.5(EN)
N17804594: C139.1 U16.6(BOOT)
N17804606: C139.2 L17.1 U16.2(SW)
N17804616: C140.1 R235.1 R237.1 U16.4(FB)
N17822498: C166.1 J11.15(SH) J11.16(SH1) R173.1
N17836581: C167.1 J18.15(SH) J18.16(SH1) R183.1

Pads without a net: J9 1; J12 1; J17 5 6 7 8 11 13 17 19 20 22 23 24 25 26 28 30 32 34 36 40 42 44 46 48 56 58 67 68 69; J19 14 15 17 18; J21 14; J22 13 14; J24 13 14 16 17 18 19 20 21; J29 1 14 24 25 30; J35 3 5 6 16 17 19 28 30 32 42 44 45 46 47 48 49 51; J36 A8 B8; J38 20 64 66 68 70 82 84 86 88 125 170 241 260 262 264 266 268 270 308 310; NOREF 1; NOREF#2 1; NOREF#3 1; NOREF#7 1; NOREF#8 1; NOREF#9 1; NOREF#11 1; NOREF#15 1; NOREF#16 1; NOREF#17 1; NOREF#18 1; NOREF#19 1; NOREF#20 1; NOREF#21 1; NOREF#22 1; NOREF#23 1; U14 4 6; U15 3; U17 1 2 3; U21 11 12 13 14; U28 2 5 6 22 23 24

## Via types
v1: diameter 0.508, hole 0.254, TOP to BOTTOM, 1799 vias

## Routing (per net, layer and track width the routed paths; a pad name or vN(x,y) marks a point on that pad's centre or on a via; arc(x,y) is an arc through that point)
1V05_AVDD_PHY0: length 26.3
  TOP w0.173: U18.8 v1(66.31,51.9) ; U18.38 70.72,49.56 v1(70.99,49.83) ; U18.3 v1(68.31,51.9)
  TOP w0.305: R114.2 v1(72.39,38.62)
  ART03 w0.305: v1(72.39,38.62) 72.95,39.18 72.95,49.5 72.62,49.83 v1(70.99,49.83) 70.99,51.6 70.69,51.9 v1(68.31,51.9)
  BOTTOM w0.305: C84.1 70.48,49.32 v1(70.99,49.83) ; R114.2 v1(72.39,38.62) ; v1(68.31,51.9) 68.12,51.9 C87.1 C86.1 66.42,51.79 v1(66.31,51.9)
1V05_AVDD_PHY1: length 26.2
  TOP w0.173: U19.3 v1(88.76,51.9) ; v1(91.44,49.83) 91.17,49.56 U19.38 ; U19.8 v1(86.76,51.9)
  TOP w0.305: R141.2 v1(92.84,38.53)
  ART03 w0.305: v1(92.84,38.53) 93.09,38.78 93.09,49.53 92.79,49.83 v1(91.44,49.83)
  BOTTOM w0.305: C106.1 90.93,49.32 v1(91.44,49.83) 91.44,51.35 90.89,51.9 v1(88.76,51.9) 88.76,51.52 88.45,51.22 C108.1 C107.1 86.87,51.79 v1(86.76,51.9) ; v1(92.84,38.53) 92.85,38.54 C105.1
1V05_DVDD_PHY0: length 18.1
  TOP w0.173: U18.21 65.51,45.11 v1(65.15,44.75)
  TOP w0.305: R113.1 v1(71.12,38.62)
  ART03 w0.305: v1(65.15,44.75) 66.95,46.55 69.8,46.55 71.12,45.23 v1(71.12,38.62)
  BOTTOM w0.305: v1(65.15,44.75) 65.66,45.26 C83.1 ; R113.1 v1(71.12,38.62)
1V05_DVDD_PHY1: length 17.7
  TOP w0.173: v1(85.6,44.75) 85.96,45.11 U19.21
  TOP w0.305: R140.1 v1(91.57,38.53)
  ART03 w0.305: v1(85.6,44.75) 86.41,43.94 86.41,37.77 87.02,37.16 90.2,37.16 v1(91.57,38.53)
  BOTTOM w0.305: v1(85.6,44.75) 86.11,45.26 C103.1 ; C104.1 91.43,38.66 v1(91.57,38.53)
1V05_PHY0: length 1.3
  TOP w0.305: C75.1 v1(74.3,40.3)
  BOTTOM w0.305: C75.1 v1(74.3,40.3)
1V05_PHY1: length 1.4
  TOP w0.305: C97.1 v1(94.74,40.3)
  BOTTOM w0.305: v1(94.74,40.3) 94.75,40.31 C96.1
1V8_DVDD_PHY0: length 41.2
  TOP w0.173: v1(68.4,44.78) 68.31,44.87 U18.28
  TOP w0.305: L10.1 62.39,39.3 C72.1 ; R107.1 v1(58.04,49.07) ; R89.1 R88.1 v1(67.69,38.62) ; C72.1 v1(63.12,38.62) ; C72.1 R90.1
  ART03 w0.305: v1(58.04,49.07) 56.82,49.07 56.24,48.48 56.24,44.57 56.9,43.91 61.26,43.91 61.72,43.46 61.72,38.92 62.03,38.62 v1(63.12,38.62) 63.72,38.02 67.09,38.02 v1(67.69,38.62) 68.28,39.2 68.28,44.65 v1(68.4,44.78)
  BOTTOM w0.305: C73.1 C81.1 67.69,45.08 68,44.78 v1(68.4,44.78) ; v1(58.04,49.07) 58.29,48.81 R102.1 R101.1
1V8_DVDD_PHY1: length 44.2
  TOP w0.173: U19.28 88.76,44.87 v1(88.85,44.78)
  TOP w0.305: L14.1 82.83,39.3 C102.1 v1(83.57,38.53) ; R116.1 R115.1 v1(88.14,38.53) ; R136.1 v1(78.49,49.07) ; R117.1 v1(90.42,38.53)
  ART03 w0.305: v1(78.49,49.07) 79.2,48.36 79.2,39.09 79.76,38.53 v1(83.57,38.53) ; v1(88.85,44.78) 87.58,43.51 87.58,39.09 v1(88.14,38.53) 88.8,37.87 89.76,37.87 v1(90.42,38.53)
  BOTTOM w0.305: v1(88.85,44.78) 88.44,44.78 88.14,45.08 C94.1 C95.1 ; R128.1 R129.1 79.51,48.04 v1(78.49,49.07) ; v1(83.57,38.53) 84.12,39.09 87.58,39.09 v1(88.14,38.53)
3V3_AVDD_PHY0: length 15.9
  TOP w0.173: U18.11 63.56,50.36 v1(63.32,50.59) ; U18.40 v1(69.81,50.93)
  TOP w0.305: L12.1 59.98,52.49 60.29,52.79 62.3,52.79 62.6,52.49 C92.1 C91.1 v1(63.32,50.59)
  ART03 w0.305: v1(69.81,50.93) 63.67,50.93 v1(63.32,50.59)
  BOTTOM w0.305: v1(69.81,50.93) 69.97,50.78 C93.1
3V3_AVDD_PHY1: length 14.9
  TOP w0.173: v1(83.77,50.59) 84,50.36 U19.11 ; U19.40 v1(90.26,50.93)
  TOP w0.305: L16.1 80.43,51.99 80.73,52.29 82.75,52.29 83.05,51.99 C113.1 C114.1 v1(83.77,50.59)
  ART03 w0.305: v1(90.26,50.93) 84.11,50.93 v1(83.77,50.59)
  BOTTOM w0.305: C112.1 90.42,50.78 v1(90.26,50.93)
3V3_DVDD_PHY0: length 103
  TOP w0.173: v1(69.4,44.78) 68.71,45.47 U18.29
  TOP w0.305: v1(64.15,44.75) 63.42,44.75 63.12,44.45 C88.1 62.39,42.96 L11.1 ; R109.2 v1(74.52,47.16) 74.78,47.16 75.08,46.86 75.08,45.44 74.78,45.13 R110.2 ; R184.1 v1(58.04,48.05)
  ART03 w0.305: v1(58.04,48.05) 58.45,47.65 58.45,45.11 58.8,44.75 v1(64.15,44.75) 64.15,44.32 64.58,43.89 65.79,43.89 67.67,45.77 68.86,45.77 69.4,45.22 v1(69.4,44.78)
  ART04 w0.305: v1(78.79,96.03) 77.13,94.37 73.66,94.37 73.05,93.76 73.05,87.96 73.66,87.35 74.98,87.35 75.59,86.74 75.59,84.6 76.2,83.99 77.7,83.99 78.31,83.38 78.31,77.06 77.86,76.61 72.32,76.61 71.2,75.48 71.2,53.69 72.01,52.88 72.01,49.68 v1(74.52,47.16)
  BOTTOM w0.305: C89.1 C90.1 ; C89.1 69.72,45.1 v1(69.4,44.78) ; C89.1 70.73,45.9 71.38,45.25 R103.1 73.03,46.55 73.63,47.16 v1(74.52,47.16) ; R28.2 77.89,96.94 v1(78.79,96.03)
3V3_DVDD_PHY1: length 86.9
  TOP w0.173: v1(89.85,44.78) 89.16,45.47 U19.29
  TOP w0.305: v1(83.57,43.73) C109.1 82.83,42.96 L15.1 ; R138.2 v1(94.97,47.16) 95.3,47.16 95.61,46.86 95.61,45.44 95.3,45.13 R139.2 ; R238.1 v1(78.49,48.05)
  ART04 w0.305: v1(83.57,43.73) 88.81,43.73 v1(89.85,44.78) ; v1(94.97,47.16) 95.83,48.03 95.83,58.92 97.18,60.27 97.18,73.1 97.94,73.86 97.94,88.85 96.18,90.61 v1(96.18,93.56)
  BOTTOM w0.305: v1(89.85,44.78) 90.17,45.1 C110.1 ; 93.92,45.49 94.23,45.79 94.23,46.42 v1(94.97,47.16) ; 93.92,45.49 91.74,45.49 91.33,45.9 C110.1 ; 93.92,45.49 94.23,45.18 R130.1 ; C110.1 C111.1 ; v1(78.49,48.05) 78.69,47.85 78.69,44.24 79.2,43.73 v1(83.57,43.73) ; R133.2 v1(96.18,93.56)
12V: length 10.6
  TOP w0.305: J29.27 149.8,29.55 ; J29.26 149.8,29.05 ; J29.29 149.8,30.55 ; J29.28 149.8,30.05
  ART04 w0.508: 20,14.97 J3.1 ; J3.1 19.27,15.7 ; J3.1 20,16.43 ; J3.1 20.73,15.7
  BOTTOM w0.305: R225.2 C27.1
  vias: v1(1.65,79.82) v1(1.65,78.82) v1(1.65,77.82) v1(2.65,79.82) v1(3.65,79.82) v1(6.1,70.4) v1(6.1,69.4) v1(6.1,68.4) v1(6.1,56.43) v1(6.1,55.43) v1(6.1,54.43) v1(6.1,42.46) v1(6.1,41.46) v1(6.1,40.46) v1(7.1,70.4) v1(7.1,69.4) v1(7.1,68.4) v1(7.1,56.43) v1(7.1,55.43) v1(7.1,54.43) v1(7.1,42.46) v1(7.1,41.46) v1(7.1,40.46) v1(9.71,80.82) v1(9.71,79.82) v1(10.71,79.82) v1(11.71,81.82) v1(11.71,80.82) v1(11.71,79.82) v1(12.71,81.82) v1(12.71,80.82) v1(12.71,79.82) v1(113.54,28.33) v1(113.54,27.33) v1(113.54,26.33) v1(115.06,28.33) v1(115.06,27.33) v1(115.06,26.33) v1(136.76,12.3) v1(136.76,11.3) v1(137.76,12.3) v1(137.76,11.3) v1(145.72,29.54) v1(146.72,29.54) v1(147.72,29.54) v1(148.72,29.54)
12V_IN: length 4.3
  TOP w1.016: 8.05,89 J39.4 ; J39.4 8.05,92.35 ; J39.4 7.08,90.67
GND: length 3311.1
  TOP w0.173: J36.A12 20.45,91.73 v1(20.56,91.61) 20.67,91.72 arc(20.73,91.81) 20.75,91.92 J36.B1 ; J38.299 v1(90.6,60.91) ; J38.141 v1(49.6,60.91) ; R126.2 v1(84.71,38.53) ; J36.B12 26.85,91.73 v1(26.96,91.61) 27.07,91.72 arc(27.13,91.81) 27.15,91.92 J36.A1 ; R99.2 v1(68.83,38.62) ; R97.2 v1(65.41,38.62) ; R125.2 v1(85.85,38.53) ; C163.2 v1(120.52,81.11) ; R127.2 v1(89.28,38.53) ; U6.4 v1(22.1,30.96)
  TOP w0.203: SS8.1 129,51.57 arc(128.58,52.59) 127.56,53.01 121.93,53.01 arc(121.85,52.99) 121.78,52.94 v1(121.69,52.85) ; 114.11,53.39 113.89,53.61 arc(113.74,53.83) 113.69,54.09 113.69,57.79 arc(113.74,58.04) 113.88,58.25 114.1,58.47
  TOP w0.305: U39.2 v1(146.71,39.92) ; v1(140.21,41.96) 140.44,41.72 arc(140.56,41.55) 140.6,41.35 C193.2 ; v1(140.15,93.3) J17.15 v1(140.15,90.75) ; U8.5 v1(50.16,17.83) ; v1(60.61,78.28) 60.44,78.11 arc(60.35,77.97) 60.32,77.81 R176.2 ; v1(56.49,76.75) 56.55,76.81 D15.1 ; J38.176 60.35,71.65 v1(60.2,71.8) 55.56,71.8 55.38,71.63 ; D12.2 v1(112.01,22.2) ; U11.15 v1(65.78,22.91) ; C113.2 v1(81.33,51.61) ; C17.2 v1(8.76,26.34) ; J26.19 v1(146.28,50.69) 133.14,50.69 arc(132.56,50.81) 132.07,51.14 129.53,53.68 arc(129.03,54.01) 128.45,54.12 v1(121.69,54.12) ; LED1.2 v1(134.35,98.39) ; v1(50.42,78.66) U31.8 U31.3 v1(50.42,76.15) 50.42,73.45 arc(50.53,73.18) 50.8,73.07 v1(52.37,73.07) v1(63.28,73.07) ; J38.116 v1(43.35,68.74) ; J38.26 20.85,71.82 v1(20.8,71.87) ; J38.53 v1(27.6,60.91) 27.6,45.44 27.52,45.35 27.52,42.63 arc(27.59,42.29) 27.78,42 v1(28.08,41.7) ; U21.9 v1(140.22,73.97) 139.98,73.97 arc(139.82,74) 139.68,74.1 C133.2 ; J38.96 v1(38.35,71.8) 38.35,72.92 ; J35.27 v1(115.1,75.31) ; J38.195 v1(64.6,60.91) 64.6,59.94 arc(64.72,59.35) 65.05,58.86 v1(68.81,55.09) ; J38.135 v1(48.1,60.91) v1(48.1,57.1) v1(48.1,49.07) v1(48.1,41.19) 48.1,37.53 arc(48.22,36.93) v1(48.56,36.42) 55.29,29.69 arc(55.49,29.56) 55.72,29.51 v1(59.44,29.51) v1(63.25,29.51) v1(67.06,29.51) v1(70.87,29.51) v1(74.68,29.51) v1(78.49,29.51) v1(82.3,29.51) v1(89.92,29.51) v1(93.73,29.51) v1(97.54,29.51) v1(101.35,29.51) v1(105.16,29.51) v1(115.59,29.51) v1(116.59,29.51) v1(117.83,29.51) v1(119.38,29.51) v1(120.4,29.51) ; v1(28.83,71.83) 28.83,72.69 ; J23.22 v1(152.81,74.93) ; v1(137.15,90.75) J17.3 v1(137.15,93.3) ; v1(73.1,55.16) 72.29,55.16 arc(71.89,55.24) 71.55,55.47 67.55,59.48 arc(67.22,59.97) 67.1,60.55 J38.205 ; v1(121.69,58.21) 129.47,58.21 arc(130.98,57.91) 132.26,57.06 133.68,55.64 arc(134.17,55.31) 134.75,55.19 v1(146.3,55.19) J26.28 ; J38.221 71.1,60.45 arc(71.19,60.02) 71.43,59.65 71.47,59.61 arc(71.84,59.37) 72.27,59.28 76.49,59.28 arc(76.71,59.24) 76.89,59.11 v1(77.1,58.91) v1(77.1,57.65) ; v1(46.35,68.74) J38.128 v1(46.35,71.96) ; J29.11 v1(150.41,21.55) ; 89.85,74.28 J38.294 ; J35.9 125.5,74.6 v1(125.48,74.57) ; C203.2 v1(97.56,19.35) ; J38.46 25.85,71.62 v1(26.04,71.8) 26.04,72.44 ; J29.18 152.15,25.05 arc(152.29,25.07) 152.4,25.15 v1(152.55,25.3) 152.41,25.44 arc(152.3,25.52) 152.16,25.55 J29.19 ; D8.2 v1(84.2,22.2) ; R74.2 v1(138.43,56.54) ; v1(138.43,56.54) v1(137.43,56.54) v1(136.43,56.54) 134.97,56.54 arc(134.39,56.65) 133.89,56.98 132.79,58.08 arc(131.33,59.06) 129.6,59.41 v1(121.69,59.41) 119.35,59.41 arc(118.85,59.61) 118.64,60.11 118.64,60.73 arc(118.56,61.13) 118.33,61.47 v1(117.98,61.83) v1(116.97,61.83) v1(115.97,61.83) v1(115.97,60.83) 115.97,58.86 arc(115.85,58.58) 115.57,58.47 114.1,58.47 ; v1(138.43,56.54) v1(139.43,56.54) v1(140.43,56.54) v1(145.3,56.54) ; v1(147.32,17.06) 146.99,17.06 ; J38.272 v1(84.35,71.96) ; v1(23.35,66.74) 23.65,67.04 arc(23.84,67.32) 23.91,67.66 23.91,68.97 23.85,69.03 J38.38 23.85,72.95 ; U22.3 v1(128.27,81.15) ; Y4.2 v1(96.4,47.78) ; J29.2 v1(150.41,17.05) ; J38.263 81.6,63.86 ; v1(149.15,93.3) J17.51 v1(149.15,90.75) ; J38.39 v1(24.1,60.91) ; v1(146.15,90.75) J17.39 v1(146.15,93.3) ; U23.3 v1(124.21,81.15) ; R7.2 v1(2.92,44.45) ; v1(20.8,71.87) 20.85,71.92 20.85,74.71 arc(21.13,75.38) 21.81,75.66 35.74,75.66 arc(36.05,75.53) 36.18,75.22 v1(36.18,73.72) 35.62,73.16 arc(34.67,72.77) 33.72,73.16 v1(33.16,73.72) 32.8,74.08 arc(32.45,74.31) 32.04,74.39 22.65,74.39 arc(22.44,74.3) 22.35,74.09 22.35,71.92 v1(22.4,71.87) 22.35,71.82 J38.32 ; v1(20.8,71.87) 20.32,71.87 arc(19.99,71.73) 19.85,71.4 J38.22 ; v1(99.08,22.65) U38.2 v1(101.03,22.65) ; U32.8 U32.3 v1(54.36,76.25) ; v1(144.65,93.3) J17.33 v1(144.65,90.75) ; 97.91,52.14 Y4.4 v1(98.8,51.11) ; v1(29.85,68.74) J38.62 29.85,72.59 ; v1(37.1,32.93) 37.1,32.94 v1(37.1,60.91) J38.91 ; C165.2 v1(112.27,79.19) ; J29.15 152.15,23.55 arc(152.29,23.57) 152.4,23.65 v1(152.55,23.8) 152.41,23.94 arc(152.3,24.02) 152.16,24.05 J29.16 ; v1(147.65,93.3) J17.45 v1(147.65,90.75) ; v1(16.23,68.74) 16.35,68.86 J38.8 16.35,72.99 ; R202.2 v1(119.63,18.92) ; J38.167 v1(57.6,60.91) 57.6,57.14 v1(57.53,57.07) 57.53,57.07 56.69,56.22 arc(56.36,55.73) 56.24,55.15 56.24,40.96 arc(56.36,40.37) 56.69,39.88 58.35,38.21 arc(58.85,37.88) 59.43,37.77 v1(105.16,37.77) v1(108.97,37.77) v1(112.86,37.77) v1(116.59,37.77) 116.93,38.11 arc(117.25,38.32) 117.64,38.4 119.96,38.4 arc(120.18,38.31) 120.27,38.1 120.27,36.15 arc(120.35,35.77) 120.56,35.44 v1(120.9,35.1) v1(124.71,35.1) arc(126.4,36.23) 128.39,36.62 136.29,36.62 arc(136.51,36.58) 136.69,36.45 v1(136.91,36.24) ; J23.19 v1(152.81,73.43) ; v1(52.85,68.74) J38.154 ; Y3.2 v1(75.7,47.78) ; U9.8 v1(37.08,17.75) ; D9.2 v1(82.68,22.2) ; J29.20 152.15,26.05 arc(152.29,26.07) 152.4,26.15 v1(152.55,26.3) 152.41,26.44 arc(152.3,26.52) 152.16,26.55 J29.21 ; Y3.4 v1(77.2,52.14) ; v1(77.2,52.14) 77.2,53.72 v1(77.1,53.83) v1(77.1,55.1) v1(77.1,56.37) ; v1(77.2,52.14) 75.13,52.14 arc(74.9,52.09) 74.7,51.96 v1(74.47,51.74) R100.2 73.78,51.77 arc(73.53,52.37) 72.92,52.62 70.74,52.62 v1(70.72,52.65) ; v1(121.69,55.39) 121.72,55.42 129.27,55.42 arc(129.86,55.31) 130.35,54.98 132.69,52.64 arc(133.18,52.31) 133.77,52.19 v1(146.3,52.19) J26.22 ; U23.8 v1(124.21,83.03) ; C176.2 139.95,70.72 139.95,70.7 v1(139.92,70.7) ; J38.249 v1(78.1,60.91) ; J38.194 v1(64.85,71.96) ; v1(40.85,68.74) J38.106 40.85,71.49 arc(40.82,71.63) 40.74,71.75 40.7,71.8 arc(40.62,71.92) 40.59,72.06 40.59,81.07 arc(40.56,81.24) 40.47,81.37 39.71,82.13 arc(39.57,82.22) 39.41,82.26 31.83,82.26 arc(31.28,82.37) 30.81,82.68 30.77,82.72 arc(30.45,83.19) 30.34,83.74 30.34,89.32 arc(30.25,89.79) 29.98,90.19 29.57,90.6 D26.2 ; J23.28 v1(152.81,77.93) ; J38.107 v1(41.1,60.91) v1(41.1,38.27) ; v1(48.85,68.74) J38.138 v1(48.85,71.96) 49.01,71.8 v1(52.37,71.8) 55.14,71.8 55.35,71.6 J38.164 ; J35.40 v1(109.9,66.85) ; J35.35 v1(111.9,75.31) ; 32.35,72.73 J38.72 v1(32.35,68.74) ; J38.24 v1(20.35,68.74) ; D13.2 v1(113.54,22.2) ; v1(138.65,93.3) J17.9 v1(138.65,90.75) ; J38.117 v1(43.6,60.91) ; J38.300 v1(91.35,71.96) 91.35,72.86 arc(91.45,73.11) 91.69,73.21 97.78,73.21 arc(98.13,73.28) 98.42,73.48 100.43,75.49 100.43,80.29 99.05,81.67 arc(98.72,82.17) 98.6,82.75 98.6,91.56 v1(98.42,91.74) 98.79,92.1 arc(99.01,92.63) 98.79,93.16 98.36,93.59 arc(97.79,93.82) 97.22,93.59 96.81,93.17 arc(96.58,92.63) 96.81,92.09 v1(97.16,91.74) 97.19,91.71 97.19,81.91 ; C78.2 v1(58.04,50.06) ; v1(100.53,77.8) 101.95,77.8 arc(102.16,77.71) 102.25,77.49 J35.53 ; v1(149.38,99.22) 149.41,99.2 U3.1 ; J38.288 88.35,69.26 arc(88.3,69.04) 88.18,68.84 v1(87.96,68.63) ; J35.43 v1(108.7,75.31) 108.7,75.12 105.31,75.12 arc(105.13,75.15) 104.99,75.25 104.95,75.29 arc(104.85,75.43) 104.82,75.61 104.82,81.15 arc(104.93,81.74) 105.26,82.23 v1(105.76,82.72) 104.99,83.49 arc(104.33,83.76) 103.66,83.49 v1(102.9,82.72) 103.3,82.32 arc(103.56,81.92) 103.66,81.45 103.66,74.52 arc(103.82,74.12) 104.22,73.96 108.65,73.96 arc(109,73.89) 109.3,73.69 v1(109.62,73.37) ; 141.86,36.02 141.86,36.03 ; v1(126.3,65.68) 126.89,65.68 arc(127.32,65.86) 127.5,66.29 J35.4 ; C202.2 v1(97.56,20.37) ; C98.2 v1(94.92,50.72) ; v1(116.59,35.1) v1(112.86,35.1) v1(108.97,35.1) v1(105.16,35.1) v1(101.35,35.1) v1(97.54,35.1) v1(93.73,35.1) v1(89.92,35.1) v1(86.11,35.1) v1(82.3,35.1) v1(78.49,35.1) v1(74.68,35.1) v1(70.87,35.1) v1(67.06,35.1) v1(63.25,35.1) v1(59.44,35.1) 58.49,35.1 arc(57.9,35.22) 57.41,35.55 54.55,38.41 arc(54.22,38.9) 54.1,39.49 v1(54.1,41.19) v1(54.1,49.07) v1(54.1,53.44) v1(54.1,57.1) v1(54.1,60.91) J38.159 ; C192.2 v1(140.6,66.1) ; J35.34 v1(112.3,66.85) ; 20.6,61.13 v1(20.86,60.87) 21,61.01 arc(21.07,61.12) 21.1,61.25 J38.27 ; v1(106.1,66.85) 105.9,67.05 J35.50 ; J38.10 16.85,72.78 ; U9.2 v1(35.81,22.95) ; U21.16 146.16,76.57 v1(146.05,76.68) ; U10.8 v1(29.59,17.75) ; 97.19,81.91 98.94,80.16 arc(99.27,79.66) 99.39,79.08 99.39,76.52 arc(99.27,75.94) 98.94,75.45 98.13,74.64 arc(97.64,74.31) 97.06,74.19 96.47,74.19 arc(96.16,74.25) 95.91,74.42 v1(95.63,74.7) ; 97.19,81.91 96.54,81.27 arc(96.05,80.93) 95.47,80.82 v1(94.61,80.82) v1(92.96,80.82) v1(90.81,80.82) v1(88.52,80.82) v1(86.23,80.82) v1(83.95,80.82) v1(74.42,80.82) v1(72.39,80.82) v1(70.1,80.82) 67.94,80.82 v1(67.82,80.69) 67.56,80.44 arc(67.41,80.2) 67.35,79.92 J38.204 ; v1(116.59,36.5) v1(112.86,36.5) v1(108.97,36.5) v1(105.16,36.5) v1(101.35,36.5) v1(97.54,36.5) v1(93.73,36.5) v1(89.92,36.5) v1(86.11,36.5) v1(82.3,36.5) v1(78.49,36.5) v1(74.68,36.5) v1(70.87,36.5) v1(67.06,36.5) v1(63.25,36.5) v1(59.44,36.5) 58.84,36.5 arc(58.35,36.59) 57.93,36.87 55.66,39.15 arc(55.33,39.64) 55.21,40.22 55.21,55.75 arc(55.31,56.24) 55.59,56.65 v1(56.01,57.07) ; R203.2 v1(116.59,18.92) ; v1(80.85,68.74) J38.258 v1(80.85,71.96) ; J38.144 v1(50.35,68.74) ; C21.2 v1(4.57,26.34) ; J23.25 152.81,76.43 ; J17.57 v1(150.65,93.3) ; v1(73.1,56.43) 72.46,56.43 arc(72.02,56.52) 71.64,56.77 69.05,59.37 arc(68.72,59.87) 68.6,60.45 J38.211 ; v1(52.32,74.34) v1(52.32,77.52) ; v1(73.35,74.67) 73.2,74.52 arc(73.12,74.41) 73.1,74.27 73.1,72.37 arc(73.12,72.23) 73.2,72.11 v1(73.35,71.96) J38.228 73.35,68.74 ; C91.2 v1(60.88,50.59) ; v1(36.85,68.74) J38.90 36.85,72.62 ; J38.311 v1(93.6,60.91) ; v1(75.85,71.96) J38.238 v1(75.85,68.74) ; v1(30.1,41.7) 30.65,42.26 arc(30.98,42.75) 31.1,43.34 v1(31.1,60.91) J38.67 ; C114.2 v1(81.33,50.59) ; v1(17.23,68.74) 17.35,68.86 J38.12 17.35,72.57 ; C204.2 v1(99.99,24.94) ; U4.1 v1(7.26,27.22) ; D6.2 v1(85.72,22.2) ; J38.81 v1(34.6,60.91) 34.6,50.83 ; 123.1,75.21 v1(123.1,75.31) J35.15 ; R121.2 v1(94.92,51.74) ; v1(140.97,37.24) 140.97,37 arc(140.74,36.44) 140.17,36.21 140.14,36.21 arc(139.56,35.97) 139.32,35.39 v1(139.32,35.35) ; J29.8 v1(150.41,20.05) ; D19.2 v1(115.06,22.2) ; J26.25 v1(146.3,53.69) ; v1(39.35,68.74) J38.100 39.35,72.05 arc(39.38,72.19) 39.46,72.31 39.5,72.35 arc(39.58,72.47) 39.61,72.62 39.61,80.27 arc(39.54,80.64) 39.33,80.95 39.28,80.99 arc(38.97,81.2) 38.6,81.28 30.91,81.28 arc(30.8,81.3) 30.7,81.37 29.44,82.63 arc(29.34,82.76) 29.31,82.93 29.31,87.74 arc(29.2,88.28) 28.9,88.74 D25.2 ; C164.2 v1(111.25,79.19) ; U22.8 v1(128.27,83.03) ; C200.2 140.6,44.59 arc(140.55,44.36) 140.42,44.17 v1(140.21,43.96) ; v1(141.65,90.75) J17.21 v1(141.65,93.3) ; C189.2 v1(140.6,63.55) ; v1(2.08,71.42) 2.09,71.41 R13.2 ; 18.85,72.77 J38.18 v1(18.85,68.74) ; v1(78.35,68.74) J38.248 v1(78.35,71.96) ; R199.2 v1(142.62,46.15) ; R70.2 v1(46.98,17.7) ; v1(92.85,71.96) J38.306 v1(92.85,68.74) ; D11.2 v1(110.49,22.2) ; U10.2 v1(28.32,22.95) ; C76.2 v1(74.47,50.72) ; 136.51,78.3 Y1.4 137.55,77.02 ; v1(143.15,90.75) J17.27 v1(143.15,93.3) ; R98.2 v1(69.98,38.62) ; Y1.2 135.01,73.62 ; J38.166 v1(57.85,68.74) ; J35.29 v1(114.3,75.31) ; 79.13,49.96 v1(78.49,49.96) ; U4.3 v1(5.96,27.22) ; J38.87 v1(36.1,60.91) ; U13.5 v1(42.55,17.83) ; R3.2 v1(2.92,58.42) ; R41.2 v1(54.6,17.7) ; v1(44.85,68.74) J38.122 v1(44.85,71.96) ; D7.2 v1(87.25,22.2) ; R108.2 v1(74.52,46.15) ; J29.5 v1(150.41,18.55) ; C99.2 v1(94.92,49.2) ; D10.2 v1(108.97,22.2) ; C172.2 v1(140.6,60.12) ; R188.1 v1(149.22,22.14) ; J38.229 v1(73.1,60.91) ; 114.11,53.39 v1(114.43,53.39) ; C42.2 v1(59.94,22.65) ; J35.21 v1(117.5,75.31) ; C92.2 v1(60.88,51.61) ; v1(56.94,99.22) v1(60.75,99.22) v1(64.56,99.22) v1(67.37,99.22) v1(68.37,99.22) v1(69.37,99.22) v1(70.37,99.22) v1(71.37,99.22) v1(72.37,99.22) v1(75.99,99.22) v1(79.8,99.22) v1(83.61,99.22) v1(87.42,99.22) v1(88.42,99.22) v1(89.42,99.22) v1(90.42,99.22) v1(91.23,99.22) v1(95.04,99.22) v1(98.85,99.22) ; J35.37 v1(111.1,75.31) ; R137.2 v1(94.97,46.15) ; C77.2 v1(74.47,49.2) ; U12.3 v1(1.77,27.22) ; J19.16 126.35,84.83 ; U12.1 v1(3.07,27.22) ; J35.18 v1(118.7,66.85)
  TOP w0.381: U3.4 v1(145.6,98.47)
  TOP w0.508: J9.4 92.98,8.71 ; J9.4 92.25,9.44 ; J9.4 91.52,8.71 ; J9.4 92.25,7.98 ; 63.95,83.77 J11.10 ; J11.10 62.98,84.75 ; J11.10 64.93,84.75 ; J11.10 63.95,85.73 ; 15.58,90.67 J39.3 ; J39.3 17.53,90.67 ; J39.3 16.55,92.35 ; J39.3 16.55,89 ; 9.27,15.7 J3.6 ; J3.6 10,14.97 ; J3.6 10.73,15.7 ; J3.6 10,16.43 ; v1(95.63,74.7) 90.51,74.7 arc(90.28,74.65) 90.09,74.53 89.85,74.28 89.48,74.65 v1(89.26,74.65) ; 73.6,13.56 J8.2 ; J8.2 74.68,12.48 ; J8.2 75.75,13.56 ; J19.13 122.05,87.18 ; J34.S1 130.36,9.18 ; J34.S1 130.36,6.72 ; J34.S1 129.13,7.95 ; 2.32,12.8 J2.3 ; J2.3 3.24,13.72 ; J2.3 1.39,13.72 ; J2.3 2.32,14.65 ; 129,21.66 SS7.1 ; SS7.1 129,27.22 ; SS7.1 131.78,24.44 ; SS7.1 126.22,24.44 ; J15.6 103.68,8.71 ; J15.6 102.95,9.44 ; J15.6 102.22,8.71 ; J15.6 102.95,7.98 ; J39.2 11.25,92.35 ; J39.2 11.25,89 ; J39.2 12.23,90.67 ; J39.2 10.28,90.67 ; 102.02,24.44 SS6.1 ; SS6.1 104.8,21.66 ; SS6.1 104.8,27.22 ; SS6.1 107.58,24.44 ; J20.4 105.11,85.5 ; J20.4 104.1,84.5 ; J20.4 104.1,86.5 ; SW3.1 18.85,10.94 ; SW3.1 18.85,9.18 ; SW3.1 17.97,10.06 ; SW3.1 19.73,10.06 ; J12.4 92.25,15.34 ; J12.4 91.52,14.62 ; J12.4 92.98,14.62 ; J12.4 92.25,13.89 ; 127.07,88.88 J19.7 126.35,89.61 ; SW1.1 8.73,10.06 ; SW1.1 7.85,10.94 ; SW1.1 7.85,9.18 ; SW1.1 6.97,10.06 ; C109.2 v1(83.57,41.19) C102.2 ; v1(73.35,78.34) v1(77.16,78.34) v1(80.97,78.34) v1(84.78,78.34) v1(95.63,78.34) ; 122.12,90.38 J19.4 ; J19.4 123.57,90.38 ; J19.4 122.85,91.11 ; J1.2 124.14,16.9 ; J1.2 123.24,16 ; J1.2 124.14,15.1 ; J1.2 125.04,16 ; 13.27,15.7 J3.4 ; J3.4 14,14.97 ; J3.4 14,16.43 ; 19.52,8.11 SW3.3 ; SW3.3 21.28,8.11 ; SW3.3 20.4,8.99 ; SW3.3 20.4,7.23 ; 56.78,90.9 J21.2 56.2,91.47 ; 127.69,7.72 J34.7 ; J34.7 127.69,9.18 ; J34.7 126.96,8.45 ; J34.7 128.42,8.45 ; 9.4,7.23 SW1.3 ; SW1.3 8.52,8.11 ; SW1.3 10.28,8.11 ; SW1.3 9.4,8.99 ; 63.25,12.48 J8.5 ; J8.5 64.32,13.56 ; J8.5 63.25,14.64 ; J8.5 62.17,13.56 ; 120.07,7.72 J34.1 ; J34.1 119.34,8.45 ; J34.1 120.8,8.45 ; J34.1 120.07,9.18 ; 19.17,75.7 J16.2 ; J16.2 19.79,76.33 ; J16.2 19.17,76.96 ; 116.17,7.95 J34.S2 ; J34.S2 117.4,9.18 ; J34.S2 117.4,6.72 ; J34.S2 118.63,7.95 ; SS11.1 20.66,25.2 ; SS11.1 17.38,21.92 ; SS11.1 14.11,25.2 ; SS11.1 17.38,28.48 ; 123.15,8.45 J34.4 ; J34.4 123.88,9.18 ; J34.4 123.88,7.72 ; J34.4 124.61,8.45 ; 142.62,8.57 SS9.1 ; SS9.1 149.18,8.57 ; SS9.1 145.9,11.85 ; J18.10 83.19,84.75 ; J18.10 81.24,84.75 ; J18.10 82.21,85.73 ; J18.10 82.21,83.77 ; v1(80.97,77.17) v1(77.16,77.17) v1(73.35,77.17) ; C72.2 v1(63.12,41.19) C88.2 ; J28.6 103.68,14.62 ; J28.6 102.95,13.89 ; J28.6 102.22,14.62 ; J28.6 102.95,15.34 ; J3.2 18.73,15.7 ; J3.2 18,14.97 ; J3.2 18,16.43 ; 14.9,7.23 SW2.3 ; SW2.3 14.02,8.11 ; SW2.3 15.78,8.11 ; SW2.3 14.9,8.99 ; J6.2 26.98,77.8 ; J6.2 26.28,78.5 ; J6.2 26.28,77.1 ; 104.8,45.81 SS5.1 ; SS5.1 104.8,51.37 ; SS5.1 107.58,48.59 ; SS5.1 102.02,48.59 ; 126.68,15.1 J1.3 ; J1.3 125.78,16 ; J1.3 127.58,16 ; J1.3 126.68,16.9 ; J20.10 105.11,88.5 ; J20.10 103.1,88.5 ; J20.10 104.1,89.5 ; J20.10 104.1,87.5 ; 12.47,10.06 SW2.1 ; SW2.1 13.35,10.94 ; SW2.1 14.23,10.06 ; SW2.1 13.35,9.18 ; v1(84.78,75.87) v1(95.63,75.87) ; SS10.1 95.46,25.2 ; SS10.1 92.18,28.48 ; SS10.1 92.18,21.92 ; 126.22,48.59 SS8.1 ; SS8.1 131.78,48.59 ; SS8.1 129,45.81 ; v1(73.35,79.54) v1(77.16,79.54) v1(80.97,79.54) v1(84.78,79.54) v1(95.63,79.54) ; C97.2 v1(94.11,38.53) ; v1(84.78,77.17) v1(95.63,77.17) ; v1(80.97,75.87) v1(77.16,75.87) v1(73.35,75.87) ; C75.2 v1(73.66,38.62)
  GND02 w0.508: J15.6 103.68,8.71 ; J15.6 102.95,7.98 ; J15.6 102.95,9.44 ; J15.6 102.22,8.71 ; J3.2 18,16.43 ; J3.2 18.73,15.7 ; J3.2 18,14.97 ; J3.2 17.27,15.7 ; 119.34,8.45 J34.1 ; J34.1 120.07,9.18 ; J34.1 120.07,7.72 ; J34.1 120.8,8.45 ; 129,21.66 SS7.1 ; SS7.1 131.78,24.44 ; SS7.1 129,27.22 ; SS7.1 126.22,24.44 ; J20.4 105.11,85.5 ; J20.4 104.1,84.5 ; J20.4 104.1,86.5 ; SS9.1 148.68,8.57 ; SS9.1 145.9,11.35 ; SS9.1 145.9,5.8 ; SS9.1 143.12,8.57 ; J18.10 83.19,84.75 ; J18.10 81.24,84.75 ; J18.10 82.21,83.77 ; J18.10 82.21,85.73 ; SS10.1 92.18,27.98 ; SS10.1 89.41,25.2 ; SS10.1 94.96,25.2 ; SS10.1 92.18,22.42 ; 126.96,8.45 J34.7 ; J34.7 127.69,9.18 ; J34.7 127.69,7.72 ; J34.7 128.42,8.45 ; J1.2 125.04,16 ; J1.2 123.24,16 ; J1.2 124.14,16.9 ; J1.2 124.14,15.1 ; 19.52,8.11 SW3.3 ; SW3.3 21.28,8.11 ; SW3.3 20.4,8.99 ; SW3.3 20.4,7.23 ; 13.27,15.7 J3.4 ; J3.4 14,14.97 ; J3.4 14.73,15.7 ; J3.4 14,16.43 ; 14.9,7.23 SW2.3 ; SW2.3 14.02,8.11 ; SW2.3 15.78,8.11 ; SW2.3 14.9,8.99 ; J39.3 17.53,90.67 ; J39.3 16.55,89 ; J39.3 16.55,92.35 ; J39.3 15.58,90.67 ; J9.4 92.25,9.44 ; J9.4 91.52,8.71 ; J9.4 92.25,7.98 ; J9.4 92.98,8.71 ; J20.10 104.1,89.5 ; J20.10 103.1,88.5 ; J20.10 105.11,88.5 ; J20.10 104.1,87.5 ; SS6.1 104.8,27.22 ; SS6.1 102.02,24.44 ; SS6.1 107.58,24.44 ; SS6.1 104.8,21.66 ; J12.4 92.25,15.34 ; J12.4 91.52,14.62 ; J12.4 92.98,14.62 ; J12.4 92.25,13.89 ; 17.38,22.42 SS11.1 ; SS11.1 20.16,25.2 ; SS11.1 17.38,27.98 ; SS11.1 14.61,25.2 ; 2.32,12.8 J2.3 ; J2.3 3.24,13.72 ; J2.3 2.32,14.65 ; J2.3 1.39,13.72 ; 56.2,91.47 J21.2 56.78,90.9 ; SS8.1 129,51.37 ; SS8.1 126.22,48.59 ; SS8.1 129,45.81 ; SS8.1 131.78,48.59 ; J8.2 75.75,13.56 ; J8.2 73.6,13.56 ; J8.2 74.68,14.64 ; J8.2 74.68,12.48 ; J19.16 126.35,86.41 ; J19.16 127.07,85.68 ; J19.16 125.62,85.68 ; J19.16 126.35,84.95 ; 102.22,14.62 J28.6 ; J28.6 103.68,14.62 ; J28.6 102.95,15.34 ; J28.6 102.95,13.89 ; 129.13,7.95 J34.S1 ; J34.S1 130.36,9.18 ; J34.S1 131.59,7.95 ; J34.S1 130.36,6.72 ; J34.S2 118.63,7.95 ; J34.S2 116.17,7.95 ; J34.S2 117.4,6.72 ; J34.S2 117.4,9.18 ; J19.13 123.57,87.18 ; J19.13 122.12,87.18 ; J19.13 122.85,87.91 ; 126.68,15.1 J1.3 ; J1.3 125.78,16 ; J1.3 127.58,16 ; J1.3 126.68,16.9 ; 102.02,48.59 SS5.1 ; SS5.1 104.8,51.37 ; SS5.1 107.58,48.59 ; SS5.1 104.8,45.81 ; 10.28,90.67 J39.2 ; J39.2 11.25,89 ; J39.2 11.25,92.35 ; J39.2 12.23,90.67 ; J8.5 63.25,14.64 ; J8.5 63.25,12.48 ; J8.5 62.17,13.56 ; J8.5 64.32,13.56 ; 19.17,75.7 J16.2 ; J16.2 19.17,76.96 ; J16.2 19.79,76.33 ; 10,14.97 J3.6 ; J3.6 9.27,15.7 ; J3.6 10,16.43 ; J3.6 10.73,15.7 ; 17.97,10.06 SW3.1 ; SW3.1 19.73,10.06 ; SW3.1 18.85,10.94 ; SW3.1 18.85,9.18 ; J34.4 124.61,8.45 ; J34.4 123.15,8.45 ; J34.4 123.88,7.72 ; J34.4 123.88,9.18 ; J11.10 63.95,85.73 ; J11.10 62.98,84.75 ; J11.10 63.95,83.77 ; J11.10 64.93,84.75 ; J19.4 122.85,91.11 ; J19.4 123.57,90.38 ; J19.4 122.12,90.38 ; SW1.1 8.73,10.06 ; SW1.1 6.97,10.06 ; SW1.1 7.85,10.94 ; SW1.1 7.85,9.18 ; 126.35,88.15 J19.7 ; J19.7 125.62,88.88 ; J19.7 127.07,88.88 ; J19.7 126.35,89.61 ; SW1.3 9.4,8.99 ; SW1.3 9.4,7.23 ; SW1.3 8.52,8.11 ; SW1.3 10.28,8.11 ; SW2.1 14.23,10.06 ; SW2.1 13.35,10.94 ; SW2.1 13.35,9.18 ; SW2.1 12.47,10.06 ; 26.28,77.1 J6.2 ; J6.2 26.28,78.5 ; J6.2 26.98,77.8
  GND02 w0.762: J21.11 54.48,85.69 ; J21.5 54.23,89.15 ; J21.8 57.33,87.43 ; J21.17 54.52,82.22
  ART03 w0.203: v1(23.35,66.74) 23.62,66.47 arc(23.88,66.29) 24.2,66.23 25.06,66.23 arc(25.59,66.45) 25.81,66.97 25.81,71.43 arc(25.83,71.56) 25.91,71.67 v1(26.04,71.8)
  ART03 w0.305: v1(116.59,18.92) v1(116.59,16.68) v1(116.59,12.87) 116.85,12.61 arc(117.09,12.45) 117.38,12.39 v1(120.5,12.39) 121.06,11.83 arc(121.95,11.47) 122.83,11.83 v1(123.39,12.39) ; v1(119.25,37.31) 118.79,36.85 arc(118.72,36.74) 118.69,36.62 118.69,36.56 arc(118.67,36.43) 118.6,36.32 117.96,35.69 arc(117.86,35.54) 117.83,35.37 v1(117.83,35.12) v1(117.83,29.51) v1(117.83,16.68) 117.83,14.12 arc(117.96,13.8) 118.29,13.66 123.06,13.66 arc(123.29,13.56) 123.39,13.33 v1(123.39,12.39) ; v1(119.25,37.31) 118.4,38.17 arc(117.69,38.46) 116.99,38.17 v1(116.59,37.77) v1(116.59,36.5) v1(116.59,35.1) 115.8,35.1 115.49,34.79 115.49,29.73 arc(115.52,29.61) v1(115.59,29.51) ; v1(119.25,37.31) 120.16,37.31 arc(120.69,37.1) 120.9,36.57 v1(120.9,35.1) 120.9,34.73 arc(120.85,34.45) 120.69,34.21 120.22,33.75 arc(119.63,32.86) 119.43,31.82 v1(119.43,28.33) v1(119.43,27.33) v1(119.43,25.82) v1(119.43,24.82) 119.43,19.13 v1(119.63,18.92) v1(119.63,16.68) 119.63,15.54 arc(119.87,14.97) 120.45,14.73 122.24,14.73 arc(122.82,14.84) 123.31,15.17 J1.2 124.97,15.17 arc(125.46,14.84) 126.04,14.73 126.39,14.73 arc(126.95,14.5) 127.18,13.94 v1(127.18,12.39) 126.62,11.83 arc(125.73,11.47) 124.84,11.83 v1(124.28,12.39) v1(123.39,12.39) ; v1(64.6,60.91) 64.6,61.32 arc(64.26,62.14) 63.44,62.48 32.77,62.48 arc(32.29,62.68) 32.1,63.15 32.1,67.33 arc(32.12,67.47) 32.2,67.59 v1(32.35,67.74) ; v1(23.35,66.74) 23.65,67.04 arc(23.84,67.32) 23.91,67.66 23.91,70.59 arc(23.79,71.17) 23.46,71.67 22.24,72.89 arc(22.17,72.99) 22.15,73.11 22.15,74.98 arc(22.05,75.48) 21.77,75.9 v1(21.34,76.32) 21.34,78.81 v1(21.22,78.94) 21.22,85.89 v1(21.01,86.1) 20.83,86.27 arc(20.74,86.42) 20.7,86.59 20.7,87.33 arc(21.06,88.19) 21.91,88.54 23.76,88.54 arc(24.23,88.63) 24.63,88.9 24.94,89.21 arc(25.04,89.28) 25.15,89.3 29.15,89.3 arc(29.45,89.36) 29.7,89.53 29.74,89.57 arc(29.91,89.83) 29.97,90.12 29.97,92.53 arc(30.05,92.93) 30.28,93.26 32.5,95.49 arc(32.83,95.98) 32.94,96.56 32.94,97.8 arc(33.07,98.1) 33.36,98.22 35.43,98.22 arc(35.96,98.11) 36.41,97.81 36.44,97.79 arc(36.73,97.09) 36.44,96.39 33.22,93.17 arc(33.15,93.06) 33.12,92.93 33.12,92.87 arc(33.1,92.74) 33.02,92.63 32.07,91.68 arc(31.74,91.18) 31.62,90.6 31.62,89.63 arc(31.56,89.32) 31.39,89.06 30.22,87.89 arc(29.96,87.72) 29.66,87.66 v1(27.86,87.66) 25.99,87.66 arc(25.59,87.58) 25.26,87.36 25.04,87.14 arc(24.9,87.05) 24.74,87.02 23.93,87.02 arc(23.29,86.75) 23.02,86.11 v1(23.02,86.1) 23.02,78.78 arc(23.14,78.2) 23.47,77.71 v1(24.85,76.32) 24.85,73.62 arc(24.97,73.03) 25.3,72.54 v1(26.04,71.8)
  ART03 w0.381: v1(115.59,29.51) 115.7,29.4 115.7,25.88 115.06,25.24 v1(115.06,22.2) 115.06,19.35 115.39,19.02 116.48,19.02 v1(116.59,18.92)
  ART03 w0.508: 92.25,7.98 J9.4 ; J9.4 92.98,8.71 ; J9.4 92.25,9.44 ; J9.4 91.52,8.71 ; 127.69,7.72 J34.7 ; J34.7 126.96,8.45 ; J34.7 127.69,9.18 ; J34.7 128.42,8.45 ; 56.78,90.9 J21.2 56.2,91.47 ; 120.07,7.72 J34.1 ; J34.1 120.07,9.18 ; J34.1 120.8,8.45 ; J34.1 119.34,8.45 ; SW2.1 14.23,10.06 ; SW2.1 13.35,10.94 ; SW2.1 12.47,10.06 ; SW2.1 13.35,9.18 ; 104.1,87.5 J20.10 ; J20.10 104.1,89.5 ; J20.10 103.1,88.5 ; J20.10 105.11,88.5 ; 129,21.66 SS7.1 ; SS7.1 129,27.22 ; SS7.1 126.22,24.44 ; SS7.1 131.78,24.44 ; 19.17,75.7 J16.2 ; J16.2 19.79,76.33 ; J16.2 19.17,76.96 ; 6.97,10.06 SW1.1 ; SW1.1 8.73,10.06 ; SW1.1 7.85,10.94 ; SW1.1 7.85,9.18 ; 126.35,88.15 J19.7 ; J19.7 126.35,89.61 ; J19.7 125.62,88.88 ; J19.7 127.07,88.88 ; 126.68,15.1 J1.3 ; J1.3 127.58,16 ; J1.3 125.78,16 ; J1.3 126.68,16.9 ; J3.2 18.73,15.7 ; J3.2 18,16.43 ; J3.2 18,14.97 ; J3.2 17.27,15.7 ; 18.85,9.18 SW3.1 ; SW3.1 17.97,10.06 ; SW3.1 19.73,10.06 ; SW3.1 18.85,10.94 ; J3.6 10.73,15.7 ; J3.6 10,16.43 ; J3.6 10,14.97 ; J3.6 9.27,15.7 ; J20.4 105.11,85.5 ; J20.4 104.1,86.5 ; J20.4 104.1,84.5 ; 143.12,8.57 SS9.1 ; SS9.1 145.9,5.8 ; SS9.1 148.68,8.57 ; SS9.1 145.9,11.35 ; 122.12,87.18 J19.13 ; J19.13 122.85,87.91 ; J19.13 123.57,87.18 ; 130.36,6.72 J34.S1 ; J34.S1 130.36,9.18 ; J34.S1 131.59,7.95 ; J34.S1 129.13,7.95 ; 14.9,7.23 SW2.3 ; SW2.3 14.9,8.99 ; SW2.3 14.02,8.11 ; SW2.3 15.78,8.11 ; SS6.1 107.58,24.44 ; SS6.1 104.8,21.66 ; SS6.1 102.02,24.44 ; SS6.1 104.8,27.22 ; 11.25,89 J39.2 ; J39.2 12.23,90.67 ; J39.2 10.28,90.67 ; J39.2 11.25,92.35 ; J19.16 126.35,86.41 ; J19.16 127.07,85.68 ; J19.16 125.62,85.68 ; 102.95,7.98 J15.6 ; J15.6 103.68,8.71 ; J15.6 102.95,9.44 ; J15.6 102.22,8.71 ; J2.3 3.24,13.72 ; J2.3 1.39,13.72 ; J2.3 2.32,14.65 ; J2.3 2.32,12.8 ; J18.10 82.21,85.73 ; J18.10 83.19,84.75 ; J18.10 81.24,84.75 ; J18.10 82.21,83.77 ; 123.88,7.72 J34.4 ; J34.4 123.88,9.18 ; J34.4 124.61,8.45 ; J34.4 123.15,8.45 ; J8.5 63.25,14.64 ; J8.5 63.25,12.48 ; J8.5 64.32,13.56 ; J8.5 62.17,13.56 ; J34.S2 117.4,9.18 ; J34.S2 117.4,6.72 ; J34.S2 118.63,7.95 ; J34.S2 116.17,7.95 ; J3.4 14,16.43 ; J3.4 13.27,15.7 ; J3.4 14.73,15.7 ; J3.4 14,14.97 ; 73.6,13.56 J8.2 ; J8.2 74.68,14.64 ; J8.2 74.68,12.48 ; J8.2 75.75,13.56 ; 89.41,25.2 SS10.1 ; SS10.1 92.18,22.42 ; SS10.1 92.18,27.98 ; SS10.1 94.96,25.2 ; J39.3 16.55,92.35 ; J39.3 15.58,90.67 ; J39.3 17.53,90.67 ; J39.3 16.55,89 ; J6.2 26.98,77.8 ; J6.2 26.28,77.1 ; J6.2 26.28,78.5 ; SW1.3 9.4,8.99 ; SW1.3 8.52,8.11 ; SW1.3 9.4,7.23 ; SW1.3 10.28,8.11 ; 14.61,25.2 SS11.1 ; SS11.1 17.38,27.98 ; SS11.1 20.16,25.2 ; SS11.1 17.38,22.42 ; J11.10 64.93,84.75 ; J11.10 63.95,85.73 ; J11.10 62.98,84.75 ; J11.10 63.95,83.77 ; 124.14,15.1 J1.2 ; J1.2 123.24,16 ; J1.2 124.14,16.9 ; J1.2 125.04,16 ; J28.6 102.95,15.34 ; J28.6 102.95,13.89 ; J28.6 102.22,14.62 ; J28.6 103.68,14.62 ; SW3.3 20.4,8.99 ; SW3.3 20.4,7.23 ; SW3.3 21.28,8.11 ; SW3.3 19.52,8.11 ; 122.12,90.38 J19.4 ; J19.4 123.57,90.38 ; J19.4 122.85,91.11 ; 91.52,14.62 J12.4 ; J12.4 92.25,13.89 ; J12.4 92.98,14.62 ; J12.4 92.25,15.34
  ART04 w0.203: v1(85.52,55.09) 85.66,55.23 85.66,73.79 ; 85.66,75.55 85.66,73.79 ; 85.66,75.55 85.66,78.24 arc(85.58,78.63) 85.36,78.96 v1(84.78,79.54) 84.68,79.64 84.68,79.88 arc(84.65,80.07) 84.54,80.22 v1(83.95,80.82) ; 85.66,75.55 v1(84.78,74.67) 85.66,73.79
  ART04 w0.305: v1(92.96,80.82) 90.95,78.81 arc(90.62,78.31) 90.51,77.73 90.51,72.81 ; v1(65.66,80.69) 65.18,80.21 65.18,72.49 arc(65.14,72.31) 65.03,72.15 v1(64.85,71.96) 65.03,71.78 arc(65.14,71.62) 65.18,71.44 65.18,55.19 v1(65.07,55.09) 65.07,54.89 arc(65.05,54.77) 64.98,54.66 v1(64.26,53.95) 64.34,53.95 65.09,53.2 arc(65.42,52.7) 65.53,52.12 65.53,51.81 arc(65.71,51.38) 66.14,51.2 69.11,51.2 arc(69.27,51.23) 69.41,51.33 69.46,51.37 arc(69.59,51.46) 69.75,51.49 70.4,51.49 arc(70.62,51.59) 70.72,51.81 v1(70.72,52.65) 70.72,52.7 70.39,53.02 arc(70.18,53.33) 70.11,53.7 70.11,76.51 v1(74.42,80.82) ; v1(67.51,55.09) v1(67.51,74.72) 67.51,77.09 arc(67.63,77.67) 67.96,78.17 69.95,80.15 arc(70.06,80.33) 70.1,80.53 v1(70.1,80.82) ; v1(85.52,55.09) 84.81,54.37 arc(84.74,54.27) 84.71,54.14 v1(84.71,53.95) 85.6,53.05 arc(85.86,52.67) 85.95,52.21 85.95,51.65 arc(86.04,51.43) 86.26,51.35 88.97,51.35 arc(89.56,51.46) 90.05,51.79 v1(91.16,52.91) 90.81,53.26 arc(90.59,53.6) 90.51,54 v1(90.51,55.09) 90.51,71.12 ; v1(90.81,80.82) 89.71,79.72 arc(89.38,79.23) 89.26,78.64 v1(89.26,55.09) ; v1(125.52,99.22) 125.51,99.23 117.91,99.23 v1(117.9,99.22) ; 90.51,72.81 v1(91.35,71.96) 90.51,71.12 ; 90.51,72.81 90.51,71.12 ; v1(68.81,55.09) 68.81,55.25 68.82,55.25 68.81,55.78 68.81,76.49 arc(68.93,77.07) 69.26,77.56 72.39,80.69 v1(72.39,80.82) ; v1(67.82,80.69) 66.77,79.64 arc(66.44,79.15) 66.32,78.56 v1(66.32,55.09) ; v1(88.52,80.82) 88.22,80.52 arc(88.03,80.23) 87.96,79.9 v1(87.96,68.63) v1(87.96,63.93) v1(87.96,55.09) ; v1(133.73,33.45) 133.73,30.83 arc(133.89,30.45) 134.26,30.3 154.89,30.3 arc(155.61,30.44) 156.22,30.85 v1(157.22,31.85) ; v1(86.23,80.82) 86.52,80.53 arc(86.7,80.26) 86.77,79.94 v1(86.77,67.64) v1(86.77,63.93) v1(86.77,55.09)
  ART04 w0.508: 15.58,90.67 J39.3 ; J39.3 17.53,90.67 ; J39.3 16.55,92.35 ; J39.3 16.55,89 ; 120.07,7.72 J34.1 ; J34.1 120.07,9.18 ; J34.1 119.34,8.45 ; J34.1 120.8,8.45 ; J39.2 11.25,92.35 ; J39.2 11.25,89 ; J39.2 10.28,90.67 ; J39.2 12.23,90.67 ; 14.9,7.23 SW2.3 ; SW2.3 14.9,8.99 ; SW2.3 15.78,8.11 ; SW2.3 14.02,8.11 ; SW2.1 14.23,10.06 ; SW2.1 13.35,9.18 ; SW2.1 13.35,10.94 ; SW2.1 12.47,10.06 ; 102.95,7.98 J15.6 ; J15.6 102.95,9.44 ; J15.6 103.68,8.71 ; J15.6 102.22,8.71 ; J34.S2 117.4,9.18 ; J34.S2 117.4,6.72 ; J34.S2 118.63,7.95 ; J34.S2 116.17,7.95 ; SW1.1 8.73,10.06 ; SW1.1 7.85,10.94 ; SW1.1 7.85,9.18 ; SW1.1 6.97,10.06 ; J2.3 2.32,14.65 ; J2.3 2.32,12.8 ; J2.3 1.39,13.72 ; J2.3 3.24,13.72 ; 62.17,13.56 J8.5 ; J8.5 64.32,13.56 ; J8.5 63.25,12.48 ; 143.12,8.57 SS9.1 ; SS9.1 148.68,8.57 ; SS9.1 145.9,5.8 ; SS9.1 145.9,11.35 ; 20.4,7.23 SW3.3 ; SW3.3 20.4,8.99 ; SW3.3 21.28,8.11 ; SW3.3 19.52,8.11 ; 127.69,7.72 J34.7 ; J34.7 127.69,9.18 ; J34.7 128.42,8.45 ; J34.7 126.96,8.45 ; 92.25,7.98 J9.4 ; J9.4 92.25,9.44 ; J9.4 92.98,8.71 ; J9.4 91.52,8.71 ; 123.88,7.72 J34.4 ; J34.4 124.61,8.45 ; J34.4 123.15,8.45 ; J34.4 123.88,9.18 ; J34.S1 130.36,9.18 ; J34.S1 131.59,7.95 ; J34.S1 129.13,7.95 ; J34.S1 130.36,6.72 ; SW1.3 9.4,8.99 ; SW1.3 9.4,7.23 ; SW1.3 10.28,8.11 ; SW1.3 8.52,8.11 ; 104.8,45.81 SS5.1 ; SS5.1 107.58,48.59 ; SS5.1 104.8,51.37 ; SS5.1 102.02,48.59 ; SW3.1 19.73,10.06 ; SW3.1 17.97,10.06 ; SW3.1 18.85,9.18 ; SW3.1 18.85,10.94 ; J8.2 75.75,13.56 ; J8.2 73.6,13.56 ; J8.2 74.68,12.48
  BOTTOM w0.173: v1(77.2,52.14) 77.6,52.14 arc(77.94,52.21) 78.22,52.4 78.92,53.09 78.98,53.09
  BOTTOM w0.203: v1(64.85,71.96) 64.85,69.79 arc(64.77,69.4) 64.55,69.07 62.58,67.1 arc(62.25,66.88) 61.86,66.8 50.79,66.8 arc(49.42,67.37) v1(48.85,68.74) ; v1(73.35,71.96) 72.72,71.96 arc(72.33,71.89) 72,71.67 65.09,64.76 arc(63.87,63.94) 62.42,63.65 49.54,63.65 arc(46.32,64.98) 44.98,68.2 44.98,68.6 v1(44.85,68.74)
  BOTTOM w0.305: C56.2 118.06,67.48 v1(118.7,66.85) ; D16.1 v1(60.61,78.28) ; C75.2 v1(73.66,38.62) ; v1(144.59,25.71) J4.6 v1(142.25,25.71) ; C48.2 70.87,20.36 v1(70.86,20.36) ; v1(46.35,68.74) 46.35,68.34 arc(47.44,65.71) 50.08,64.61 61.63,64.61 arc(63.48,64.98) 65.05,66.03 67.81,68.79 arc(68.1,69.22) 68.2,69.73 68.2,70.05 arc(68.29,70.52) 68.55,70.91 71.97,74.33 arc(72.25,74.52) 72.59,74.58 arc(72.76,74.65) 72.95,74.67 v1(73.35,74.67) v1(77.16,74.67) v1(80.97,74.67) v1(84.78,74.67) 93.81,74.67 arc(94.39,74.79) 94.88,75.12 v1(95.63,75.87) ; v1(28.32,22.95) 28.32,24.63 arc(28.23,24.84) 28.02,24.93 C41.2 ; 123.33,92.5 R155.2 ; v1(152.7,52.78) J22.4 ; U25.2 v1(27.86,86.66) ; v1(37.63,75.55) D31.2 C216.2 ; C138.2 v1(111.4,97.19) ; v1(77.1,56.37) 77.1,56.31 77.16,56.37 77.61,56.37 arc(77.98,56.44) 78.29,56.65 78.54,56.89 arc(80.03,57.89) 81.8,58.24 ; v1(77.1,55.1) 77.67,55.1 arc(78.15,55.19) 78.55,55.46 79.3,56.21 arc(80.36,56.92) 81.61,57.17 117.51,57.17 arc(117.62,57.14) 117.72,57.08 117.77,57.03 arc(117.83,56.93) 117.86,56.82 v1(117.86,56.05) ; v1(94.11,38.53) 93.95,38.68 arc(93.87,38.8) 93.84,38.95 C105.2 ; C40.2 v1(25.78,17.75) ; C100.2 92.72,80.43 arc(92.74,80.56) 92.82,80.67 v1(92.96,80.82) ; v1(121.69,59.41) v1(121.69,58.21) v1(121.69,56.79) v1(121.69,55.39) v1(121.69,54.12) v1(121.69,52.85) ; R216.2 v1(40.14,97.7) ; C55.2 106.16,66.79 v1(106.1,66.85) ; v1(111.1,75.31) 111.24,75.45 C58.2 ; v1(89.28,38.53) 89.28,38.99 arc(89.37,39.2) 89.59,39.29 C104.2 ; 123.88,11.9 124.28,12.31 v1(124.28,12.39) 124.59,12.69 arc(124.87,12.89) 125.21,12.95 126.25,12.95 arc(126.59,12.89) 126.87,12.69 v1(127.18,12.39) 127.45,12.11 arc(127.63,11.85) 127.69,11.55 J34.7 127.69,6.27 arc(127.55,5.92) 127.2,5.78 v1(124.69,5.78) 124.37,5.78 arc(124.2,5.81) 124.05,5.91 123.88,6.08 ; 123.88,11.9 v1(123.39,12.39) 123.09,12.69 arc(122.8,12.89) 122.47,12.95 121.42,12.95 arc(121.09,12.89) 120.8,12.69 v1(120.5,12.39) 120.26,12.16 arc(120.12,11.94) 120.07,11.69 J34.1 120.07,7.13 arc(120.17,6.63) 120.45,6.2 v1(120.88,5.78) 123.39,5.78 arc(123.56,5.81) 123.71,5.91 123.88,6.08 ; 123.88,11.9 J34.4 123.88,6.08 ; v1(73.35,71.96) v1(75.85,71.96) v1(78.35,71.96) v1(80.85,71.96) ; J22.21 150.33,61.28 v1(150.28,61.23) ; D32.2 v1(31.71,77.54) ; R220.2 v1(28.83,71.83) ; U17.4 v1(14.1,80.82) v1(14.1,81.82) ; C96.2 v1(97.41,40.31) ; D30.2 v1(45.71,81.2) 45.71,78.56 arc(45.83,77.98) 46.16,77.48 47.11,76.53 R215.2 v1(48.01,76.37) ; v1(64.85,71.96) 69.61,76.72 arc(70.1,77.05) 70.68,77.17 v1(73.35,77.17) v1(77.16,77.17) v1(80.97,77.17) v1(84.78,77.17) 92.09,77.17 arc(92.67,77.28) 93.16,77.61 94.93,79.38 arc(95.11,79.5) 95.33,79.54 v1(95.63,79.54) 95.82,79.73 arc(95.92,79.89) 95.96,80.08 95.96,80.8 arc(95.99,80.94) 96.06,81.05 96.1,81.09 arc(96.22,81.16) 96.35,81.19 113.94,81.19 arc(114.4,81.1) 114.79,80.84 v1(115.19,80.44) ; C213.2 v1(39.4,93.01) ; R234.2 28.72,75.48 arc(28.56,75.71) 28.51,75.97 Q4.2 ; C30.2 v1(138.46,23.52) C28.2 ; D20.1 v1(24.77,84.73) ; C22.2 v1(35.51,34.77) ; v1(114.43,53.39) 114.08,53.39 arc(113.81,53.44) 113.59,53.59 112.54,54.64 arc(112.04,54.97) 111.46,55.09 v1(98.58,55.09) v1(90.51,55.09) v1(89.26,55.09) v1(87.96,55.09) v1(86.77,55.09) v1(85.52,55.09) 81.61,55.09 arc(81.02,54.97) 80.53,54.64 78.98,53.09 ; v1(65.78,17.32) 65.79,17.33 C45.2 ; J16.2 19.47,76.03 arc(19.66,75.75) 19.72,75.41 D24.1 ; Y2.2 v1(116.46,94.53) ; v1(64.56,99.22) 64.09,98.75 arc(64,98.62) 63.97,98.45 R27.2 ; v1(84.35,71.96) v1(91.35,71.96) v1(92.85,71.96) 100.27,71.96 v1(100.38,72.07) ; v1(109.72,70.61) 109.4,70.29 arc(109.1,70.09) 108.74,70.02 100.35,70.02 arc(100.05,69.89) 99.92,69.59 99.92,68.12 v1(100.03,68.02) 100.18,67.86 102.11,67.86 v1(102.26,68.01) 102.78,68.53 arc(103.27,68.86) 103.86,68.98 112.61,68.98 arc(113.19,69.09) 113.68,69.42 114.42,70.16 arc(114.5,70.27) 114.52,70.41 v1(114.52,70.61) ; v1(77.1,53.83) 77.93,53.83 arc(78.28,53.9) 78.58,54.09 79.84,55.35 arc(80.78,55.98) 81.88,56.2 114.6,56.2 arc(114.92,56.14) 115.18,55.96 v1(115.47,55.67) ; v1(77.2,52.14) 75.13,52.14 arc(74.9,52.09) 74.7,51.96 v1(74.47,51.74) 73.51,51.74 arc(73.22,51.86) 73.1,52.14 v1(73.1,55.16) v1(73.1,56.43) v1(73.1,57.7) 73.1,58.82 arc(73.23,59.13) 73.53,59.25 76.54,59.25 arc(76.74,59.21) 76.9,59.1 v1(77.1,58.91) arc(78.53,59.86) 80.21,60.19 ; C23.2 v1(31.25,35.6) ; C137.2 v1(113.02,94.16) ; L2.2 v1(13.97,96.31) ; R69.2 v1(45.09,22.4) ; C52.2 v1(136.02,38.27) ; R40.2 v1(52.7,22.4) ; 38.35,71.88 v1(38.35,71.8) ; D17.1 v1(59.02,78.28) ; v1(95.63,77.17) 95.26,77.17 arc(94.98,77.11) 94.73,76.95 94.1,76.31 arc(93.6,75.98) 93.02,75.87 v1(84.78,75.87) v1(80.97,75.87) v1(77.16,75.87) v1(73.35,75.87) 71.96,75.87 arc(71.47,75.77) 71.05,75.49 67.27,71.71 arc(67.11,71.47) 67.06,71.19 arc(66.82,70) 66.14,68.98 63.75,66.59 arc(62.71,65.9) 61.49,65.66 50.69,65.66 arc(48.5,66.56) v1(47.59,68.75) ; U30.3 U30.8 v1(107.06,89.8) ; C16.2 v1(149.35,95.83) ; v1(83.61,99.22) 82.43,99.22 82.26,99.05 R131.2 ; C116.2 C115.2 ; C67.2 v1(21.22,78.94) ; D29.2 v1(41.99,81.2) ; R212.2 v1(38.47,97.7) ; C153.2 v1(102.23,96.06) ; v1(150.28,59.78) J22.18 v1(152.7,59.78) ; v1(43.05,75.23) 43.05,74.95 41.65,73.54 arc(41.15,73.21) 40.57,73.1 37.21,73.1 arc(36.83,73.17) 36.51,73.39 v1(36.18,73.72) 35.85,73.39 arc(35.53,73.17) 35.15,73.1 34.19,73.1 arc(33.81,73.17) 33.49,73.39 v1(33.16,73.72) ; v1(124.3,64.68) 124.04,64.42 arc(123.88,64.18) 123.83,63.9 R17.2 ; v1(77.1,57.65) 77.1,57.73 77.42,57.73 arc(77.65,57.78) 77.85,57.91 arc(79.31,58.89) 81.03,59.23 ; C146.2 v1(122.17,94.41) ; C15.2 v1(148.21,95.83) ; U14.5 144.4,39.04 ; C158.2 v1(112.88,98.34) ; U15.2 139.7,39.32 arc(139.65,39.06) 139.5,38.84 139.2,38.54 C47.2 v1(138.52,38.27) ; C31.2 v1(76.32,80.81) ; C37.2 v1(33.27,17.75) ; C51.2 v1(136.02,40.81) ; Y2.4 v1(113.03,96.83) ; C38.2 v1(34.54,25.78) ; Z1.2 v1(7.49,16.18) ; C57.2 v1(130.94,70.53) ; D18.1 56.23,76.75 v1(56.49,76.75) ; Z2.2 v1(7.49,18.84)
  BOTTOM w0.508: 92.25,7.98 J9.4 ; J9.4 92.25,9.44 ; J9.4 92.98,8.71 ; J9.4 91.52,8.71 ; 62.17,13.56 J8.5 ; J8.5 63.25,12.48 ; J8.5 63.25,14.64 ; J8.5 64.32,13.56 ; SS11.1 17.38,27.98 ; SS11.1 14.61,25.2 ; SS11.1 20.16,25.2 ; SS11.1 17.38,22.42 ; J20.4 104.1,86.5 ; J20.4 104.1,84.5 ; J20.4 105.11,85.5 ; SW2.1 14.23,10.06 ; SW2.1 13.35,9.18 ; SW2.1 13.35,10.94 ; SW2.1 12.47,10.06 ; 89.41,25.2 SS10.1 ; SS10.1 92.18,22.42 ; SS10.1 94.96,25.2 ; 125.62,88.88 J19.7 ; J19.7 126.35,88.15 ; J19.7 126.35,89.61 ; J19.7 127.07,88.88 ; 126.68,15.1 J1.3 ; J1.3 126.68,16.9 ; J1.3 127.58,16 ; J1.3 125.78,16 ; 145.9,5.8 SS9.1 ; SS9.1 143.12,8.57 ; SS9.1 145.9,11.35 ; SS9.1 148.68,8.57 ; 129.13,7.95 J34.S1 ; J34.S1 130.36,9.18 ; J34.S1 131.59,7.95 ; J34.S1 130.36,6.72 ; J2.3 2.32,14.65 ; J2.3 1.39,13.72 ; J2.3 3.24,13.72 ; J2.3 2.32,12.8 ; J12.4 92.98,14.62 ; J12.4 91.52,14.62 ; J12.4 92.25,15.34 ; J12.4 92.25,13.89 ; SW2.3 14.9,8.99 ; SW2.3 15.78,8.11 ; SW2.3 14.9,7.23 ; SW2.3 14.02,8.11 ; 19.17,75.7 J16.2 ; J16.2 19.79,76.33 ; J16.2 19.17,76.96 ; 20.4,7.23 SW3.3 ; SW3.3 20.4,8.99 ; SW3.3 19.52,8.11 ; 18,14.97 J3.2 ; J3.2 18.73,15.7 ; J3.2 17.27,15.7 ; J3.2 18,16.43 ; 8.52,8.11 SW1.3 ; SW1.3 9.4,8.99 ; SW1.3 9.4,7.23 ; SW1.3 10.28,8.11 ; J3.4 14,16.43 ; J3.4 14.73,15.7 ; J3.4 14,14.97 ; J3.4 13.27,15.7 ; J39.2 12.23,90.67 ; J39.2 11.25,92.35 ; J39.2 11.25,89 ; J39.2 10.28,90.67 ; J19.4 123.57,90.38 ; J19.4 122.12,90.38 ; J19.4 122.85,91.11 ; SS8.1 131.78,48.59 ; SS8.1 126.22,48.59 ; SS8.1 129,45.81 ; 102.02,24.44 SS6.1 ; SS6.1 107.58,24.44 ; SS6.1 104.8,27.22 ; SS6.1 104.8,21.66 ; SW3.1 19.73,10.06 ; SW3.1 18.85,9.18 ; SW3.1 18.85,10.94 ; SW3.1 17.97,10.06 ; SS5.1 107.58,48.59 ; SS5.1 102.02,48.59 ; SS5.1 104.8,45.81 ; SS5.1 104.8,51.37 ; J18.10 83.19,84.75 ; J18.10 82.21,85.73 ; J18.10 82.21,83.77 ; J18.10 81.24,84.75 ; 10,14.97 J3.6 ; J3.6 10,16.43 ; J3.6 9.27,15.7 ; J3.6 10.73,15.7 ; 125.62,85.68 J19.16 ; J19.16 127.07,85.68 ; J19.16 126.35,84.95 ; J19.16 126.35,86.41 ; J11.10 64.93,84.75 ; J11.10 62.98,84.75 ; J11.10 63.95,83.77 ; J11.10 63.95,85.73 ; 16.55,89 J39.3 ; J39.3 17.53,90.67 ; J39.3 15.58,90.67 ; J39.3 16.55,92.35 ; J28.6 103.68,14.62 ; J28.6 102.95,15.34 ; J28.6 102.22,14.62 ; J28.6 102.95,13.89 ; U24.2 124.46,94.53 v1(124.34,94.41) C144.2 C145.2 123.33,92.5 ; 126.22,24.44 SS7.1 ; SS7.1 131.78,24.44 ; SS7.1 129,27.22 ; SS7.1 129,21.66 ; J1.2 125.04,16 ; J1.2 124.14,15.1 ; J1.2 123.24,16 ; J8.2 75.75,13.56 ; J8.2 74.68,12.48 ; J8.2 73.6,13.56 ; J8.2 74.68,14.64 ; J34.S2 117.4,9.18 ; J34.S2 118.63,7.95 ; J34.S2 117.4,6.72 ; J34.S2 116.17,7.95 ; 120.8,8.45 J34.1 119.34,8.45 ; J19.13 123.57,87.18 ; J19.13 122.12,87.18 ; J19.13 122.85,87.91 ; 103.1,88.5 J20.10 ; J20.10 104.1,89.5 ; J20.10 104.1,87.5 ; 102.95,7.98 J15.6 ; J15.6 103.68,8.71 ; J15.6 102.95,9.44 ; J15.6 102.22,8.71 ; SW1.1 7.85,10.94 ; SW1.1 6.97,10.06 ; SW1.1 7.85,9.18 ; SW1.1 8.73,10.06 ; U26.2 129.03,94.53 v1(128.91,94.41) C148.2 C149.2 127.9,92.5 R157.2 ; 126.96,8.45 J34.7 128.42,8.45 ; J6.2 26.28,78.5 ; J6.2 26.98,77.8 ; J6.2 26.28,77.1 ; 56.2,91.47 J21.2 56.78,90.9 ; 124.61,8.45 J34.4 123.15,8.45
  vias: v1(0.78,92.85) v1(0.78,89.04) v1(0.78,85.23) v1(0.78,81.42) v1(0.78,76.34) v1(0.78,73.8) v1(0.78,71.99) v1(0.78,70.99) v1(0.78,69.99) v1(0.78,68.99) v1(0.78,67.99) v1(0.78,66.18) v1(0.78,62.37) v1(0.78,58.56) v1(0.78,54.75) v1(0.78,50.94) v1(0.78,47.13) v1(0.78,43.32) v1(0.78,42.32) v1(0.78,41.32) v1(0.78,39.51) v1(0.78,35.7) v1(0.78,31.89) v1(0.78,28.08) v1(0.78,20.46) v1(0.78,16.65) v1(0.78,12.84) v1(1.71,84.82) v1(1.71,83.82) v1(1.77,22.04) v1(1.92,44.45) v1(2.26,55.29) v1(2.44,69.21) v1(2.71,84.82) v1(2.71,83.82) v1(3,22.14) v1(3.71,84.82) v1(3.71,83.82) v1(3.81,24.56) v1(5.1,51.43) v1(5.1,37.2) v1(5.71,84.82) v1(5.71,83.82) v1(5.65,79.82) v1(5.65,78.82) v1(5.96,28.22) v1(6.1,67.4) v1(6.1,66.4) v1(6.1,65.4) v1(6.1,64.4) v1(6.1,53.43) v1(6.1,52.43) v1(6.1,51.43) v1(6.1,50.43) v1(6.1,39.46) v1(6.1,38.2) v1(6.1,37.2) v1(6.6,21.11) v1(6.58,5.78) v1(6.71,84.82) v1(6.71,83.82) v1(6.65,79.82) v1(6.65,78.82) v1(7.1,67.4) v1(7.1,66.4) v1(7.1,65.4) v1(7.1,64.4) v1(7.1,53.43) v1(7.1,52.43) v1(7.1,51.43) v1(7.1,50.43) v1(7.1,39.46) v1(7.1,38.2) v1(7.1,37.2) v1(7.1,36.21) v1(7.6,21.11) v1(7.71,84.82) v1(7.71,83.82) v1(7.65,79.82) v1(7.65,74.82) v1(7.65,73.82) v1(8.1,39.46) v1(8.1,38.2) v1(8.1,37.2) v1(8.1,36.2) v1(8.08,23.59) v1(8.71,84.82) v1(8.71,83.82) v1(8.65,79.82) v1(8.65,74.82) v1(8.65,73.82) v1(9.1,39.46) v1(9.1,38.2) v1(9.1,37.2) v1(9.1,36.2) v1(9.71,85.82) v1(9.71,84.82) v1(9.71,83.82) v1(9.65,74.82) v1(9.65,73.82) v1(10.39,5.78) v1(10.53,72.21) v1(10.53,71.21) v1(10.71,85.82) v1(10.71,84.82) v1(10.71,83.82) v1(11.02,44.24) v1(11.23,36.17) v1(11.53,72.21) v1(11.53,71.21) v1(11.71,85.82) v1(11.71,84.82) v1(11.71,83.82) v1(11.99,57.06) v1(11.99,53.25) v1(11.99,49.44) v1(12.71,85.82) v1(12.71,84.82) v1(12.71,83.82) v1(13.97,95.31) v1(14.2,5.78) v1(14.97,96.31) v1(14.97,95.31) v1(15.8,57.06) v1(15.8,53.25) v1(15.8,49.44) v1(15.8,45.63) v1(15.8,41.82) v1(16.23,67.74) v1(16.23,66.74) v1(16.23,65.74) v1(16.23,64.74) v1(17.23,67.74) v1(17.23,66.74) v1(17.23,65.74) v1(17.23,64.74) v1(17.83,57.06) v1(17.83,53.25) v1(17.83,49.44) v1(17.83,45.63) v1(17.83,41.82) v1(18.01,5.78) v1(19.86,60.87) v1(19.86,57.06) v1(19.86,53.25) v1(19.86,49.44) v1(19.86,45.63) v1(19.86,41.82) v1(20.56,90.81) v1(20.56,90.01) v1(20.56,89.21) v1(20.84,63.9) v1(20.86,57.06) v1(20.86,53.25) v1(20.86,49.44) v1(20.86,45.63) v1(20.86,41.82) v1(21.82,5.78) v1(22.65,99.22) v1(23.01,15.21) v1(23.6,42.51) v1(23.77,84.73) v1(23.77,83.73) v1(24.61,89.25) v1(25.63,5.78) v1(25.76,84.73) v1(25.76,83.73) v1(26.46,99.22) v1(27.71,26.67) v1(27.76,92.41) v1(27.76,91.61) v1(27.86,85.66) v1(27.86,84.66) v1(28.38,77.26) v1(28.56,92.41) v1(28.56,91.61) v1(29.36,92.41) v1(29.36,91.61) v1(29.36,90.61) v1(29.38,77.26) v1(29.44,5.78) v1(30.27,99.22) v1(30.56,78.86) v1(32.62,90.68) v1(32.62,89.68) v1(33.25,5.78) v1(34.08,99.22) v1(34.11,38.12) v1(34.16,67.74) v1(36.1,58.91) v1(36.85,67.74) v1(37.06,5.78) v1(37.89,99.22) v1(38.35,67.74) v1(40.87,5.78) v1(41.7,99.22) v1(42.67,36.39) v1(42.7,31.87) v1(43.54,25.95) v1(43.71,72.92) v1(44.7,75.23) v1(44.68,5.78) v1(45.51,99.22) v1(47.57,65.6) v1(47.8,99.12) v1(48.49,5.78) v1(48.79,35.23) v1(49.17,25.95) v1(49.28,66.01) v1(49.56,57.15) v1(49.56,55.01) v1(49.56,53.49) v1(49.58,51.89) v1(49.56,48.97) v1(50.42,86.15) v1(50.6,36.45) v1(51.16,25.95) v1(52.3,5.78) v1(52.7,28.61) v1(53.13,99.22) v1(53.7,28.61) v1(53.7,27.61) v1(54.7,28.61) v1(54.7,27.61) v1(55.4,79.45) v1(56.11,5.78) v1(57.12,41.19) v1(58.12,41.19) v1(58.39,53.56) v1(58.59,67.74) v1(59.92,5.78) v1(60.12,41.19) v1(60.35,67.74) v1(60.6,59.91) v1(60.99,57.88) v1(61.12,41.19) v1(62.6,59.91) v1(63.42,51.63) v1(63.73,5.78) v1(64.85,72.96) v1(64.82,67.66) v1(64.8,46.15) v1(64.87,75.28) v1(65.07,78.13) v1(66.31,49.56) v1(66.31,48.56) v1(66.31,47.56) v1(67.31,49.56) v1(67.31,48.56) v1(67.31,47.56) v1(67.54,5.78) v1(68.31,49.56) v1(68.31,48.56) v1(68.31,47.56) v1(69.19,79.5) v1(69.88,78.1) v1(70.01,74.39) v1(70.01,72.34) v1(70.86,21.36) v1(71.35,5.78) v1(71.86,22.36) v1(71.86,21.36) v1(72.86,22.36) v1(72.86,21.36) v1(73.86,22.36) v1(73.86,21.36) v1(74.09,15.55) v1(75.07,20.36) v1(75.07,19.36) v1(75.07,18.36) v1(75.09,16.55) v1(75.09,15.55) v1(75.16,5.78) v1(75.29,40.3) v1(75.52,44.12) v1(76.1,59.91) v1(76.09,16.55) v1(76.09,15.55) v1(77.09,22.85) v1(77.09,21.85) v1(77.09,20.85) v1(77.09,19.85) v1(77.09,18.85) v1(77.09,17.68) v1(77.09,16.55) v1(77.09,15.55) v1(78.13,45.78) v1(78.13,44.78) v1(78.13,43.78) v1(78.09,18.85) v1(78.09,17.68) v1(78.09,16.55) v1(78.09,15.55) v1(78.3,39.8) v1(78.97,5.78) v1(79.09,18.85) v1(79.09,17.68) v1(79.09,16.55) v1(79.09,15.55) v1(80.57,41.19) v1(80.63,14.51) v1(81.09,17.68) v1(81.6,63.93) v1(81.57,41.19) v1(81.63,16.51) v1(81.63,14.51) v1(81.63,13.51) v1(81.63,12.51) v1(82.57,41.19) v1(83.82,51.69) v1(85.19,46) v1(86.59,5.78) v1(86.76,49.56) v1(86.76,48.56) v1(86.76,47.56) v1(87.76,49.56) v1(87.76,48.56) v1(87.76,47.56) v1(88.76,49.56) v1(88.76,48.56) v1(88.76,47.56) v1(89.26,63.93) v1(90.4,5.78) v1(94.21,5.78) v1(95.23,84.56) v1(95.23,83.56) v1(95.23,82.56) v1(96.23,84.56) v1(96.23,83.56) v1(96.23,82.56) v1(97.92,52.5) v1(97.97,47.49) v1(98.02,5.78) v1(98.58,89.2) v1(100.41,60.91) v1(101.83,5.78) v1(102.66,99.22) v1(103.24,72.07) v1(105.47,99.22) v1(105.64,5.78) v1(106.17,18.33) v1(106.47,99.22) v1(106.9,95.46) v1(106.9,94.66) v1(106.9,93.86) v1(107.57,18.35) v1(107.7,95.46) v1(107.7,94.66) v1(107.7,93.86) v1(108.5,95.46) v1(108.5,94.66) v1(108.5,93.86) v1(109.26,99.12) v1(109.45,5.78) v1(111.9,25.32) v1(113.26,5.78) v1(114.53,73.37) v1(115.6,13.31) v1(115.97,63.83) v1(115.97,62.83) v1(115.95,11.43) v1(116.23,53.34) v1(116.97,62.83) v1(117.07,5.78) v1(117.47,80.44) v1(117.98,62.83) v1(118.47,80.44) v1(118.8,52.96) v1(119.47,80.44) v1(120.43,28.33) v1(120.43,27.33) v1(120.43,25.82) v1(121.43,28.33) v1(121.43,27.33) v1(121.41,20.61) v1(121.79,38.5) v1(121.87,37.11) v1(122.43,28.33) v1(122.43,27.33) v1(123.43,28.33) v1(123.43,27.33) v1(124.42,28.33) v1(124.42,27.33) v1(125.3,65.68) v1(125.3,64.68) v1(125.3,63.68) v1(125.42,28.33) v1(125.42,27.33) v1(126.2,94.41) v1(126.17,93.4) v1(126.17,92.35) v1(126.3,64.68) v1(126.39,60.65) v1(127.2,94.41) v1(127.17,93.4) v1(127.17,92.35) v1(128.5,5.78) v1(129.33,99.22) v1(130.27,83.03) v1(131.27,83.03) v1(131.29,5.88) v1(131.45,73.23) v1(132.31,40.66) v1(132.45,70.72) v1(133.14,99.22) v1(133.45,70.72) v1(133.73,34.84) v1(133.76,20.3) v1(133.76,19.3) v1(134.01,83.03) v1(134.45,73.23) v1(134.45,71.72) v1(134.45,70.72) v1(134.45,69.72) v1(134.76,20.3) v1(134.76,19.3) v1(135.13,63.73) v1(135.13,62.73) v1(135.13,61.73) v1(135.13,60.73) v1(135.45,73.23) v1(135.45,71.72) v1(135.45,70.72) v1(135.45,69.72) v1(136.13,63.73) v1(136.13,62.73) v1(136.53,34.59) v1(136.76,8.3) v1(136.76,7.3) v1(136.76,6.3) v1(136.95,99.22) v1(136.93,88.08) v1(137.54,78.68) v1(137.54,76.68) v1(137.76,16.3) v1(137.76,15.3) v1(137.76,8.3) v1(137.76,7.3) v1(137.76,6.3) v1(137.94,86.15) v1(138.3,32.5) v1(138.63,72.06) v1(138.76,16.3) v1(138.76,15.3) v1(139.43,57.54) v1(139.76,16.3) v1(139.76,15.3) v1(139.93,5.78) v1(140.72,86.15) v1(140.76,99.22) v1(141.64,13.3) v1(141.73,86.15) v1(141.76,32.51) v1(142.37,82.72) v1(142.76,32.51) v1(143.08,63.61) v1(143.59,36.24) v1(143.76,32.51) v1(143.97,86.78) v1(144.02,19.22) v1(144.08,63.61) v1(144.4,82.72) v1(144.4,79.93) v1(144.57,99.22) v1(144.64,13.3) v1(144.71,43.91) v1(144.71,36.24) v1(144.66,21.39) v1(144.76,32.51) v1(145.55,23.79) v1(145.71,38.24) v1(145.71,37.24) v1(145.72,25.75) v1(146.56,82.72) v1(146.56,79.93) v1(146.63,71.34) v1(146.69,69.72) v1(146.69,67.01) v1(146.69,65.88) v1(146.69,62.82) v1(146.69,61.82) v1(146.71,44.91) v1(146.71,43.91) v1(146.71,38.24) v1(146.71,37.24) v1(146.72,25.75) v1(146.76,15.3) v1(146.86,86.78) v1(147.32,18.59) v1(147.72,25.75) v1(148.72,35.04) v1(148.72,34.04) v1(148.72,25.75) v1(149.26,80.98) v1(149.26,79.98) v1(149.28,71.43) v1(149.28,70.31) v1(149.28,68.01) v1(149.28,67.01) v1(149.28,63.83) v1(149.28,62.83) v1(149.28,61.23) v1(149.28,59.78) v1(149.35,45.22) v1(149.35,43.22) v1(149.35,42.22) v1(149.35,41.22) v1(149.41,16.3) v1(149.41,15.3) v1(149.41,14.3) v1(149.72,35.04) v1(149.72,34.04) v1(149.78,86.78) v1(149.76,32.51) v1(150.26,80.98) v1(150.28,70.31) v1(150.28,68.01) v1(150.28,67.01) v1(150.28,63.83) v1(150.28,62.83) v1(150.35,45.22) v1(150.35,42.22) v1(150.35,41.22) v1(150.41,15.3) v1(150.41,14.3) v1(150.76,32.51) v1(151.41,15.3) v1(151.41,14.3) v1(151.36,5.78) v1(152.07,89.85) v1(152.19,99.22) v1(152.7,67.53) v1(152.7,65.53) v1(152.7,64.53) v1(152.7,57.78) v1(152.85,44.22) v1(152.85,43.22) v1(152.85,42.22) v1(154.07,89.85) v1(154.71,79.42) v1(154.71,77.9) v1(154.71,76.5) v1(154.71,74.98) v1(154.71,73.45) v1(157.22,92.81) v1(157.22,89) v1(157.22,85.19) v1(157.22,81.38) v1(157.22,77.57) v1(157.22,73.76) v1(157.22,69.95) v1(157.22,66.14) v1(157.22,62.33) v1(157.22,58.52) v1(157.22,54.71) v1(157.22,50.9) v1(157.22,43.28) v1(157.22,39.47) v1(157.22,35.66) v1(157.22,28.04) v1(157.22,24.23) v1(157.22,20.42) v1(157.22,16.61) v1(157.22,12.8)
